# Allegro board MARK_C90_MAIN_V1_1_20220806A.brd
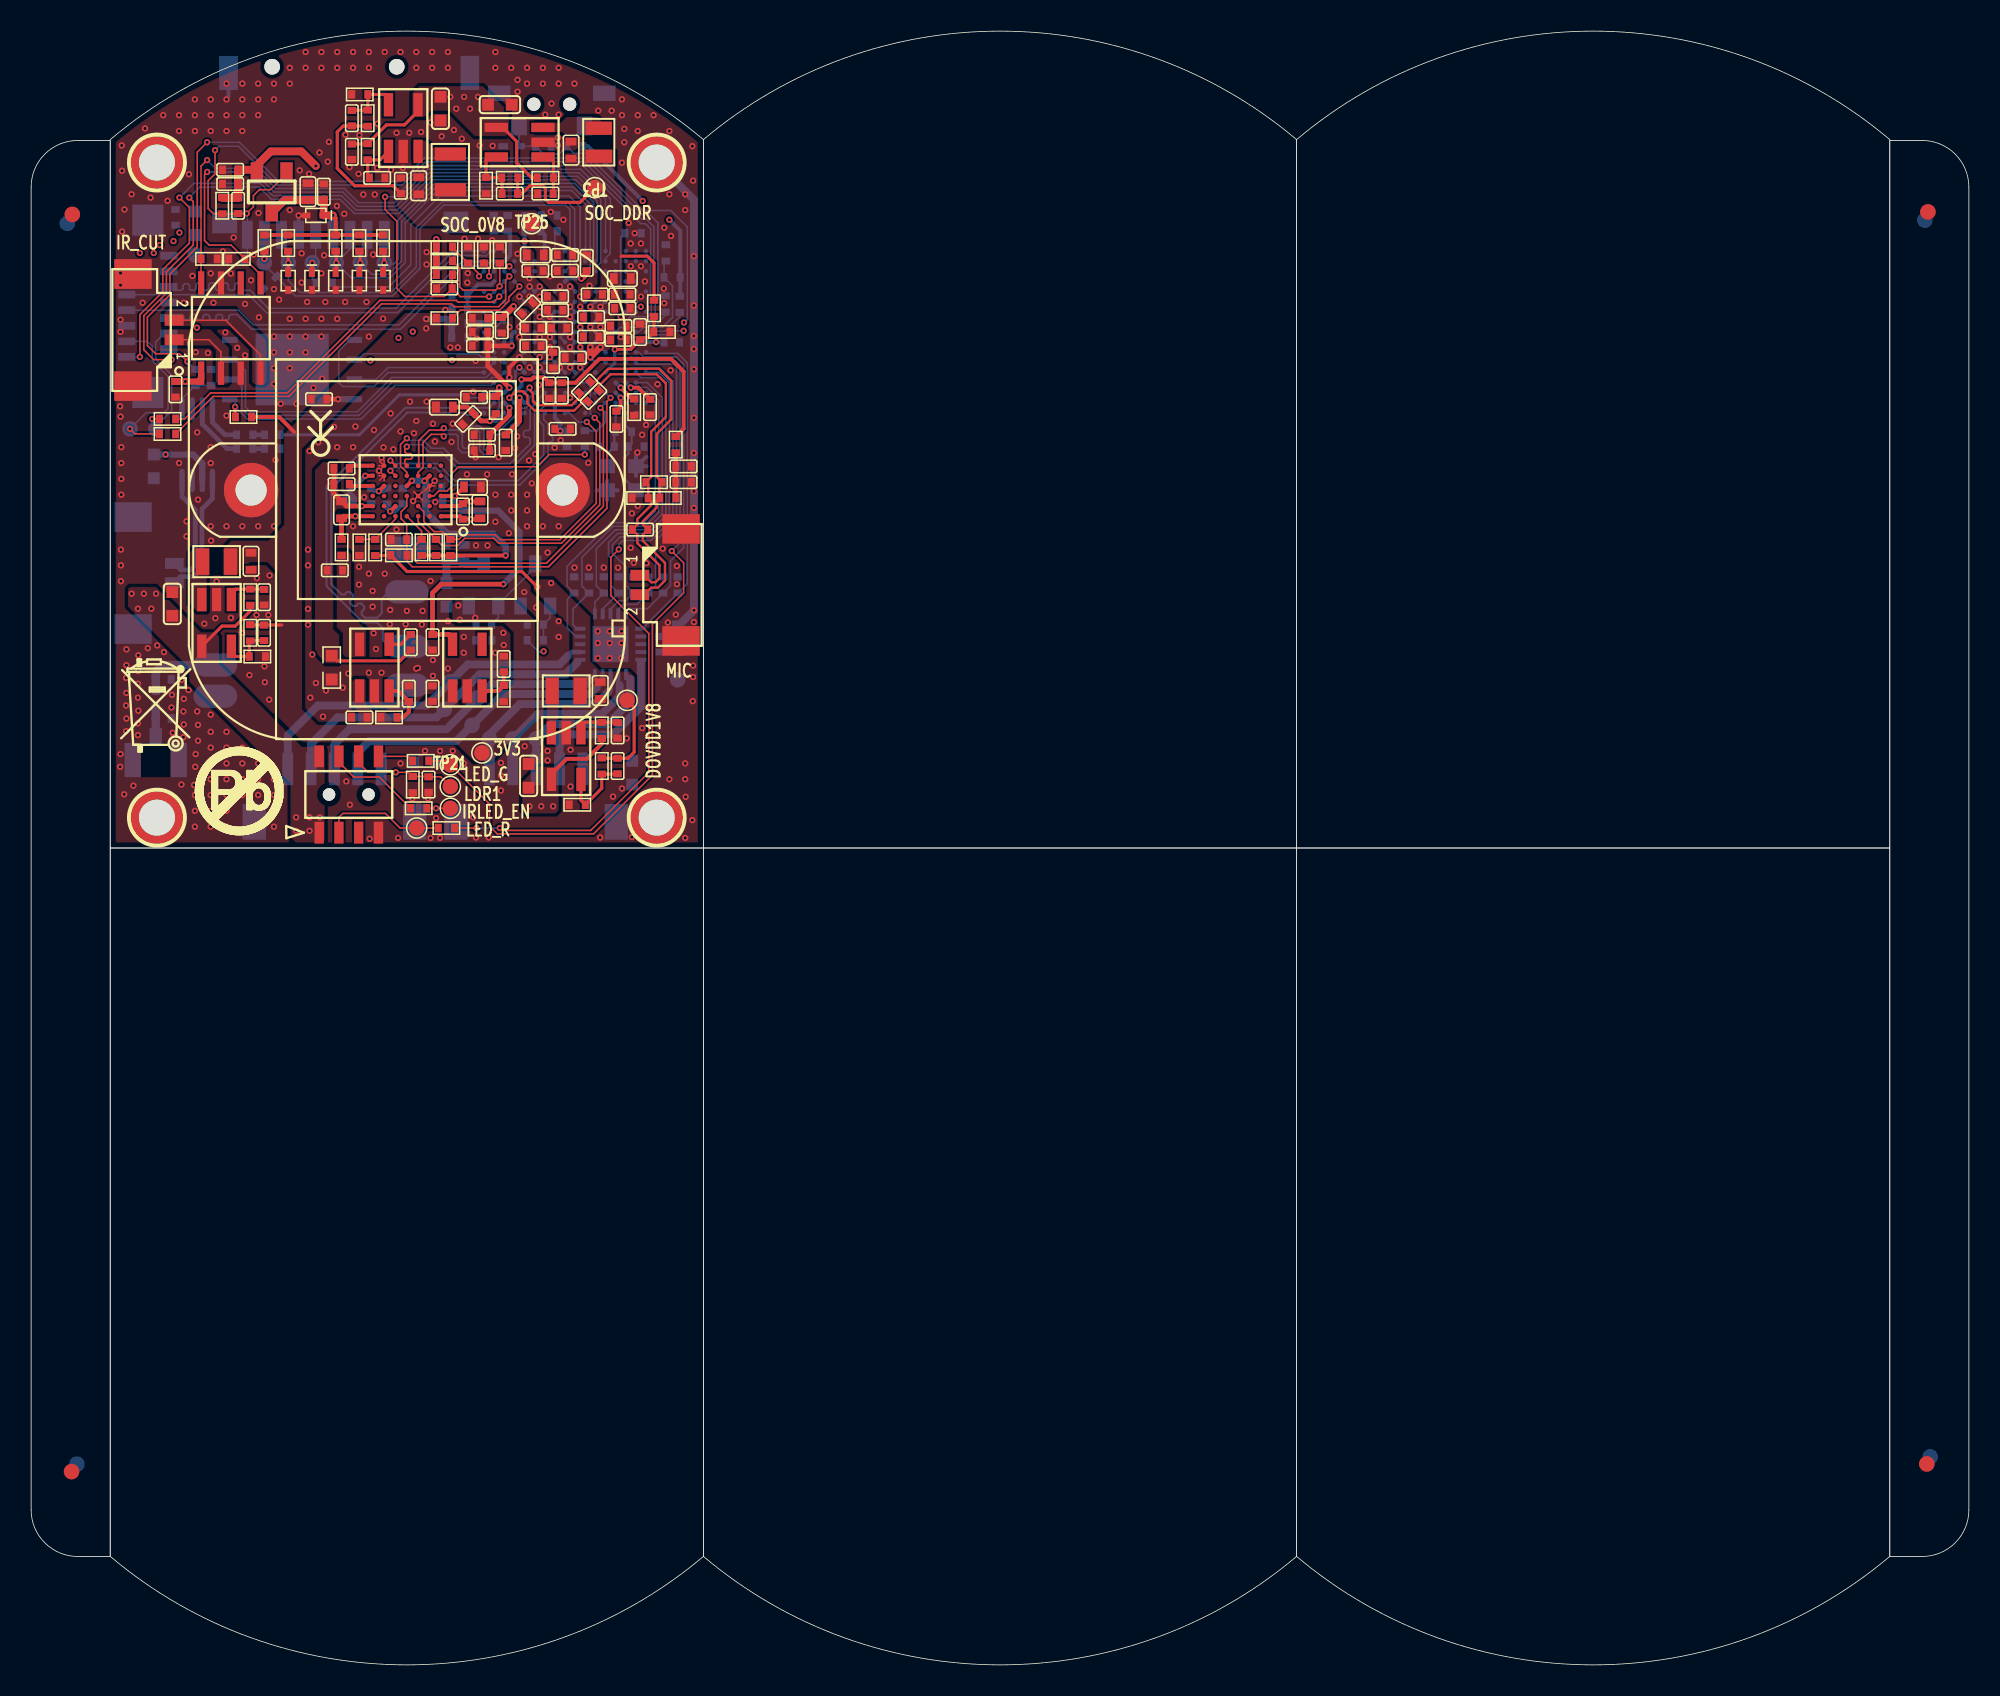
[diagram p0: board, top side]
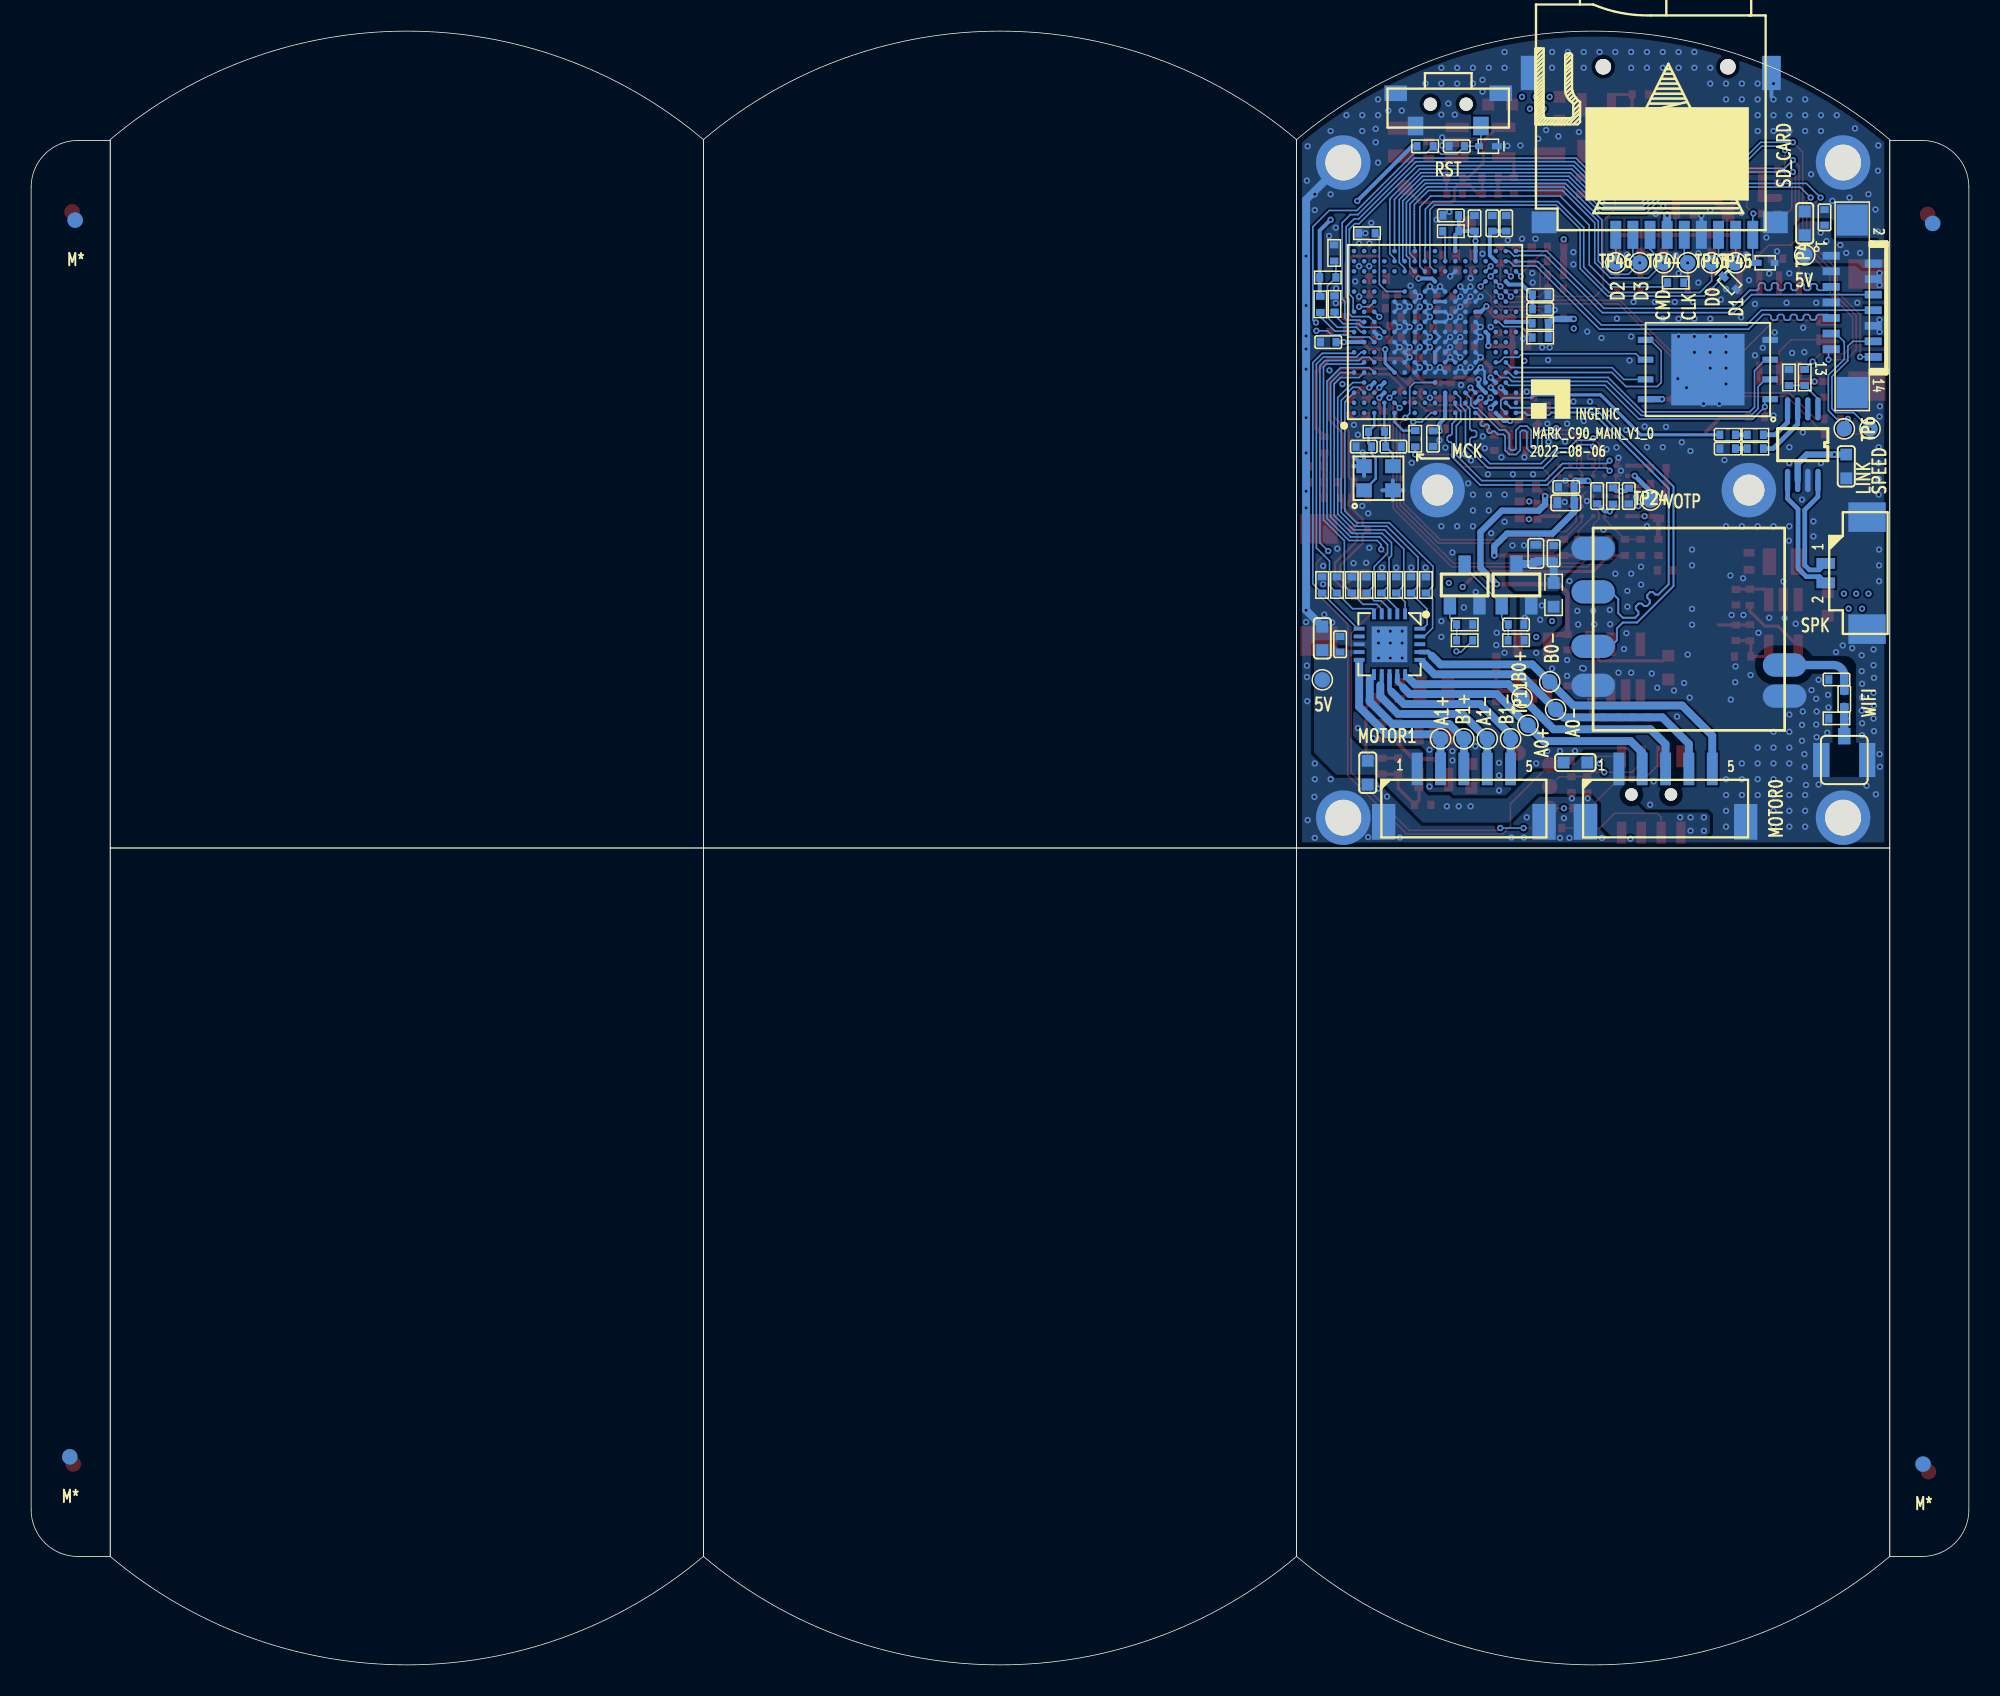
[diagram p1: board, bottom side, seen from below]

Outline 124.46 x 104.99 mm; copper layers: TOP, L2_PWR, L3_GND, BOTTOM. Coordinates in mm from the lower left corner of the outline.
Outline path: 5.08,52.5 5.08,98.02 arc(24.13,104.99) 43.18,98.02 ; 5.08,52.5 5.08,6.97 arc(24.13,0) 43.18,6.97 ; 5.08,52.5 43.18,52.5 ; 5.08,52.5 43.18,52.5 ; 43.18,98.02 43.18,52.5 ; 43.18,98.02 arc(62.23,104.99) 81.28,98.02 ; 43.18,98.02 43.18,52.5 ; 43.18,52.5 43.18,6.97 ; 43.18,52.5 81.28,52.5 ; 43.18,52.5 43.18,6.97 ; 43.18,52.5 81.28,52.5 ; 81.28,98.02 81.28,52.5 ; 81.28,98.02 arc(100.33,104.99) 119.38,98.02 119.38,52.5 ; 81.28,98.02 81.28,52.5 ; 43.18,6.97 arc(62.23,0) 81.28,6.97 ; 81.28,52.5 81.28,6.97 ; 81.28,52.5 119.38,52.5 ; 81.28,52.5 81.28,6.97 ; 81.28,52.5 119.38,52.5 ; 81.28,6.97 arc(100.33,0) 119.38,6.97 119.38,52.5 ; 0,94.97 0,9.96 arc(0.88,7.84) 3,6.97 5.08,6.97 5.08,97.96 3,97.96 arc(0.88,97.09) 0,94.97 ; 119.38,97.96 119.38,6.97 121.46,6.97 arc(123.58,7.84) 124.46,9.96 124.46,94.97 arc(123.58,97.09) 121.46,97.96 119.38,97.96

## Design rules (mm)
net group ENTH_R: nets RD_N RD_P
net group ENTH_T: nets TD_N TD_P
net group MICNL: nets MICNL MINNL
net group MICPL: nets MICPL MINPL
net group USB_D: nets USB_DM USB_DP
net group MIPI_CSI: nets CSI_CLKN CSI_CLKP CSI_DATAN0 CSI_DATAN1 CSI_DATAP0 CSI_DATAP1
net group POWER: nets VDDMSC0

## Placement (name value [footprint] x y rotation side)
C1  10uF/10V-0603  [C0603]  9.07 68.18 90 top
C2  10uF/6.3V  [C0402_E]  24.89 95.05 90 top
C3  100nF/10V  [C0402]  14.96 68.61 270 top
C4  100nF/6.3V  [C0402]  23.75 95.05 90 top
C5  22pF/50V  [C0402]  14.96 66.33 270 top
C6  22pF/50V  [C0402]  20.6 99.4 270 top
C7  10uF/6.3V  [C0402_E]  14.12 70.92 270 top
C8  10uF/10V-0603  [C0603]  26.29 100.01 270 top
C9  100nF/10V  [C0402]  20.6 97.24 270 top
C10  100nF/10V  [C0402]  22.22 95.56 0 top
C11  22pF/50V  [C0402]  37.67 57.77 270 top
C12  10uF/6.3V  [C0402_E]  36.55 62.62 270 top
C13  10uF/10V-0603  [C0603]  31.95 57.13 90 top
C14  100nF/10V  [C0402]  37.67 60.05 270 top
C15  22pF/50V  [C0402]  30.74 94.55 180 top
C16  10uF/6.3V  [C0402_E]  34.68 97.34 90 top
C17  100nF/6.3V  [C0402]  18.49 81.34 0 top
C18  10uF/10V-0603  [C0603]  30.11 100.27 0 top
C20  100nF/10V  [C0402]  33.03 94.55 180 top
C21  12pF/50V  [C0402]  38.86 78.29 180 bottom
C22  100pF/50V  [C0402]  39.12 72.96 0 top
C23  100nF/6.3V  [C0402]  41.91 77.02 0 top
C24  4.7uF/6.3V  [C0402]  41.91 76 0 top
C25  12pF/50V  [C0402]  36.96 78.29 0 bottom
C26  3.3nF/50V  [C0402]  15.49 78.16 0 bottom
C27  3.3nF/50V  [C0402]  15.49 79.05 0 bottom
C28  10uF/10V-0603  [C0603]  7.87 77.02 270 bottom
C29  10uF/10V-0603  [C0603]  25.27 57.99 0 bottom
C30  10uF/10V-0603  [C0603]  10.54 92.64 90 bottom
C31  1uF/6.3V  [C0402]  9.27 81.97 270 top
C32  2.2uF/10V  [C0402]  19.94 75.88 0 top
C33  2.2uF/10V  [C0402]  19.94 76.89 0 top
C34  100nF/6.3V  [C0402]  31.75 92.64 90 bottom
C35  100nF/6.3V  [C0402]  23.62 72.32 0 top
C36  100nF/10V  [C0402]  9.27 93.02 270 bottom
C37  1uF/6.3V  [C0402]  19.51 70.34 180 top
C38  100nF/6.3V  [C0402]  24.26 62.41 90 top
C39  100nF/6.3V  [C0402]  23.88 75.11 90 bottom
C40  10uF/6.3V  [C0402_E]  19.94 74.23 90 top
C41  10uF/6.3V  [C0402_E]  28.83 74.23 90 top
C42  100nF/6.3V  [C0402]  27.74 74.12 90 top
C43  10uF/6.3V  [C0402_E]  25.89 74.68 0 bottom
C44  100nF/6.3V  [C0402]  25.86 75.7 0 bottom
C45  10uF/6.3V  [C0402_E]  28.35 75.7 0 top
C46  100nF/6.3V  [C0402]  21.84 75.11 270 bottom
C47  1uF/6.3V  [C0402]  25.78 65.72 270 top
C48  100nF/6.3V  [C0402]  33.66 87.05 180 top
C49  1uF/6.3V  [C0402]  25.78 62.41 90 top
C50  100nF/6.3V  [C0402]  30.35 64.32 90 top
C51  10uF/10V-0603  [C0603]  41.53 65.97 90 bottom
C52  10nF/6.3V  [C0402]  24.38 65.72 270 top
C53  100nF/6.3V  [C0402]  28.07 80.07 225 top
C54  10uF/6.3V  [C0402_E]  26.54 80.83 180 top
C58  100nF/10V  [C0402]  40.39 65.59 90 bottom
C61  100nF/6.3V  [C0402]  32.26 84.77 0 top
C63  100nF/6.3V  [C0402]  28.45 81.46 180 top
C65  100nF/6.3V  [C0402]  28.83 84.77 180 top
C66  4.7uF/6.3V  [C0402]  28.96 79.05 180 top
C67  100nF/6.3V  [C0402]  28.96 78.04 180 top
C68  4.7uF/6.3V  [C0402]  33.27 81.9 270 top
C69  100nF/6.3V  [C0402]  34.09 81.9 270 top
C70  100nF/6.3V  [C0402]  35.56 82.1 45 top
C71  100nF/6.3V  [C0402]  36.12 81.54 45 top
C72  100nF/6.3V  [C0402]  32.89 97.59 0 bottom
C73  100nF/10V  [C0402]  25.53 56.57 270 top
C74  100nF/6.3V  [C0402]  29.72 92.64 90 bottom
C75  1uF/6.3V  [C0402]  21.08 60.89 180 top
C76  1uF/6.3V  [C0402]  30.61 92.64 90 bottom
C77  10uF/10V-0603  [C0603]  38.61 57.33 270 bottom
C79  100nF/6.3V  [C0402]  27.53 87.13 180 bottom
C83  10pF/50V  [C0402]  8 62.08 270 bottom
C84  10uF/6.3V  [C0402_E]  27.81 71.43 90 bottom
C86  100nF/6.3V  [C0402]  30.48 78.54 270 top
C88  100nF/6.3V  [C0402]  34.42 78.8 270 bottom
C89  100nF/6.3V  [C0402]  26.67 71.43 90 bottom
C90  100nF/6.3V  [C0402]  34.29 89.59 180 top
C91  1uF/6.3V  [C0402]  29.08 66.86 180 bottom
C96  100nF/6.3V  [C0402]  39.75 80.83 270 top
C97  5.6pF/50V  [C0402]  8.5 63.33 180 bottom
C140  100nF/6.3V  [C0402]  28.83 86.54 180 top
C143  1uF/6.3V  [C0402]  30.23 86.09 270 top
C144  100nF/6.3V  [C0402]  35.69 90.1 90 top
C146  10uF/6.3V  [C0402_E]  17.78 94.67 90 top
C147  100nF/6.3V  [C0402]  18.8 94.67 90 top
C148  4.7uF/6.3V  [C0402]  12.78 96.08 180 top
C149  100nF/6.3V  [C0402]  12.78 95.17 180 top
C150  1uF/6.3V  [C0402]  13.29 93.77 270 top
C175  1uF/6.3V  [C0402]  27.53 88.04 180 bottom
C176  100nF/6.3V  [C0402]  26.54 88.45 180 top
C187  100nF/6.3V  [C0402]  34.14 79.43 0 top
C189  100nF/6.3V  [C0402]  28.83 85.66 180 top
C203  10uF/6.3V  [C0402_E]  32.38 90.61 180 top
C206  100nF/6.3V  [C0402]  33.91 85.91 180 top
C212  100nF/6.3V  [C0402]  31.88 87.18 45 top
C213  100nF/6.3V  [C0402]  34.29 90.61 0 top
C214  100nF/6.3V  [C0402]  32.38 89.59 180 top
C215  100nF/6.3V  [C0402]  33.66 87.94 180 top
C216  100nF/6.3V  [C0402]  32.26 85.91 0 top
C217  10nF/6.3V  [C0402]  33.53 83.85 90 top
C218  10nF/6.3V  [C0402]  34.8 84 0 top
C231  100nF/6.3V  [C0402]  37.72 86.04 0 top
C232  100nF/6.3V  [C0402]  37.97 87.18 0 top
C233  10uF/6.3V  [C0402_E]  37.97 89.08 0 top
C234  100nF/6.3V  [C0402]  35.97 86.62 180 top
C238  100nF/6.3V  [C0402]  37.72 85.15 0 top
C239  100nF/6.3V  [C0402]  35.97 85.35 180 top
C240  10nF/6.3V  [C0402]  36.2 88.07 180 top
C241  10nF/6.3V  [C0402]  37.97 88.07 0 top
C244  100nF/6.3V  [C0402]  39.12 85.66 270 top
C248  100nF/6.3V  [C0402]  37.59 80.07 270 top
C250  100nF/6.3V  [C0402]  41.15 85.01 0 bottom
C255  100nF/6.3V  [C0402]  33.27 93.15 0 bottom
D1  ESD5451X  [ESD0402]  30.86 97.59 0 bottom
D2  ESD5451X  [ESD0402]  18.29 93.15 180 top
D3  ESD5451X  [ESD0402]  18.03 88.96 270 top
D4  ESD5451X  [ESD0402]  19.56 88.96 270 top
D5  ESD5451X  [ESD0402]  16.51 88.96 270 top
D6  ESD5451X  [ESD0402]  15.37 88.83 225 bottom
D7  ESD5451X  [ESD0402]  22.61 88.96 270 top
D8  ESD5451X  [ESD0402]  21.08 88.96 270 top
D9  ESD5451X  [ESD0402]  13.08 90.1 180 bottom
FB7  1000ohm/250mA  [FB0402]  29.84 80.96 270 top
HOLE1  T POINT R  [H3D5MM_2D2MM]  8.08 54.45 0 top
HOLE2  T POINT R  [H3D5MM_2D2MM]  40.18 96.55 0 top
HOLE3  T POINT R  [H3D5MM_2D2MM]  8.08 96.55 0 top
HOLE4  T POINT R  [H3D5MM_2D2MM]  40.18 54.45 0 top
J1  CON2 1.25mm LT  [CON2-1D25-LT]  41.19 69.4 90 top
J2  CON2 1.25mm LT  [CON2-1D25-LT]  7.09 70.16 90 bottom
J3  CON14 0.5mm LT  [FPC-CON14-0D5-LT]  7.49 87.31 270 bottom
J4  CON2 1.25mm LT  [CON2-1D25-LT]  7.09 85.78 270 top
J5  Sensor  [IRCUT-32X28-16_8X14_9]  24.13 75.5 270 top
J6  CON5 1.5mm LT  [CON5-1D5-LT]  19.48 55.03 180 bottom
J7  CON5 1.5mm LT  [CON5-1D5-LT]  32.44 55.03 180 bottom
J8  CON8 1.27mm Female  [HEADER4X2FM_1D27_SMD]  20.4 55.93 0 top
J9  IPEX  [ANT3_U_FL_R_SMD]  8 58.15 0 bottom
J32  MICROSD_TF  [TFCARD]  20.43 92.1 0 bottom
L1  2.2uH/2.2A-2520  [L2520]  26.92 95.94 270 top
L2  2.2uH/1.3A-2016  [L2016]  11.91 70.9 180 top
L3  2.2uH/1.3A-2016  [L2016]  34.37 62.59 180 top
L4  2.2uH/1.3A-2016  [L2016]  36.46 97.85 90 top
L5  -  [L0402]  8.5 60.83 0 bottom
M*  -  [unnamed#2]  2.94 12.9 180 bottom
M*#2  -  [unnamed#2]  121.98 13.37 180 bottom
M*#3  -  [unnamed#2]  121.63 92.84 180 bottom
NOREF  -  []  43.21 101.99 0 top
NOREF#2  -  [unnamed#2]  2.6 12.42 0 top
NOREF#3  -  []  102.02 0.05 90 top
NOREF#4  -  []  -8.59 51.34 0 top
NOREF#5  -  [unnamed#2]  2.65 93.21 0 top
NOREF#6  -  []  169.66 233.61 0 top
NOREF#7  -  []  10.54 61.77 0 top
NOREF#8  -  [unnamed#2]  121.83 93.37 0 top
NOREF#9  -  [unnamed#2]  121.76 12.91 0 top
NOREF#10  -  []  5.41 101.89 0 top
NOREF#11  -  []  70.28 210.17 0 top
NOREF#12  -  []  -81.64 -109 0 top
NOREF#13  -  []  119.25 99.96 0 top
NOREF#14  -  []  81 103.03 0 top
NOREF#15  -  []  0 9.96 0 top
NOREF#16  -  [unnamed#2]  2.32 92.63 180 bottom
NOREF#17  -  []  26.86 81.35 180 bottom
Q1  WPM3401  [SOT23]  15.45 94.66 180 top
Q2  WPM3401  [SOT23]  29.06 69.4 180 bottom
Q3  SST3904  [SOT23]  32.38 69.4 180 bottom
R1  100K  [R0402]  14.07 68.61 90 top
R2  100K  [R0402]  21.62 97.24 270 top
R3  150K/1%  [R0402]  14.07 66.33 90 top
R4  33.2K/1%  [R0402]  14.53 64.8 180 top
R5  100K/1%  [R0402]  21.62 99.4 270 top
R6  300K/1%  [R0402]  21.11 100.92 180 top
R7  100K  [R0402]  36.65 60.05 90 top
R8  200K/1%  [R0402]  36.65 57.77 90 top
R9  100K/1%  [R0402]  35.08 55.28 0 top
R10  100K  [R0402]  33.03 95.57 0 top
R11  150K/1%  [R0402]  30.74 95.57 0 top
R12  10K  [R0402]  13.64 80.19 0 top
R13  120K/1%  [R0402]  29.22 95.06 90 top
R14  33R  [R0402]  38.73 80.83 270 top
R15  2.2K  [R0402]  39.12 74.99 180 top
R16  10K  [R0402]  27.53 86.21 180 bottom
R17  1M  [R0402]  38.05 79.25 0 bottom
R18  10K  [R0402]  40 76 0 top
R19  2.2K  [R0402]  40.89 74.99 180 top
R20  0R  [R0402]  41.4 78.42 90 top
R21  10K  [R0402]  11.56 82.73 90 bottom
R22  0R  [R0402]  10.54 82.73 270 bottom
R23  10K  [R0402]  27.53 85.3 180 bottom
R24  68K/1%  [R0402]  13.72 78.16 0 bottom
R26  68K/1%  [R0402]  13.72 79.05 0 bottom
R27  0R  [R0402]  22.86 75.11 270 bottom
R28  10K  [R0402]  11.43 90.35 0 top
R29  10K  [R0402]  13.21 90.35 180 top
R30  4.7K  [R0402]  26 71.81 90 top
R32  4.7K  [R0402]  26.93 71.81 90 top
R33  10K  [R0402]  25.08 71.81 90 top
R34  10K  [R0402]  23.62 71.3 0 top
R35  10K  [R0402]  22.1 71.81 90 top
R36  4.7K  [R0402]  21.08 71.81 90 top
R37  0R  [R0402]  19.94 71.81 90 top
R38  150K  [R0402]  22.99 60.89 0 top
R39  0R-0603  [R0603]  19.3 64.09 270 top
R40  100K  [R0402]  30.35 62.41 90 top
R42  100K  [R0402]  34.87 69.4 90 bottom
R43  100K  [R0402]  35.83 69.4 90 bottom
R44  100K  [R0402]  36.78 69.4 270 bottom
R45  100K  [R0402]  37.73 69.4 270 bottom
R46  100K  [R0402]  38.68 69.4 270 bottom
R47  100K  [R0402]  39.64 69.4 270 bottom
R48  100K  [R0402]  40.59 69.4 270 bottom
R49  100K  [R0402]  41.54 69.4 270 bottom
R50  1K  [R0402]  28.07 90.61 90 top
R51  10K  [R0402]  26.54 91.12 180 top
R52  10K  [R0402]  26.54 89.34 180 top
R53  10K  [R0402]  34.92 97.59 180 bottom
R54  0R  [R0402]  26.67 53.78 180 top
R55  1K  [R0402]  24.89 55.05 180 top
R56  0R  [R0402]  25.02 58.1 0 top
R57  33R  [R0402]  35.56 78.8 90 bottom
R58  33.2K/1%  [R0402]  24.51 56.57 90 top
R59  100K  [R0402]  41.66 87.43 90 bottom
R60  100K  [R0402]  41.17 89.16 0 bottom
R61  100K  [R0402]  40.77 90.74 270 bottom
R68  0R-0603  [R0603]  26.67 68.76 90 bottom
R69  100K  [R0402]  29.08 65.84 180 bottom
R70  1K  [R0402]  32.38 65.84 0 bottom
R71  10K  [R0402]  32.38 66.86 0 bottom
R75  240R/1%  [R0402]  40.74 87.46 90 bottom
R99  300R  [R0402]  8.76 80.07 0 top
R100  300R  [R0402]  8.76 79.1 0 top
R207  33R  [R0402]  18.83 88.83 0 bottom
R209  100K  [R0402]  16.51 91.37 270 top
R210  100K  [R0402]  19.56 91.37 270 top
R211  100K  [R0402]  14.99 91.37 270 top
R212  100K  [R0402]  22.61 91.37 270 top
R213  100K  [R0402]  21.08 91.37 270 top
R214  100K  [R0402]  12.28 93.77 270 top
R312  2.49K/1%  [R0402]  29.08 90.61 90 top
R313  10K  [R0402]  26.54 86.54 180 top
R314  10K  [R0402]  26.54 90.23 180 top
R315  1K  [R0402]  30.1 90.61 90 top
R343  1K  [R0402]  33.27 92.13 0 bottom
R345  240R/1%  [R0402]  38.66 92.01 0 bottom
R346  10K/1%  [R0402]  40 87.18 90 top
R347  10K/1%  [R0402]  40.51 85.66 180 top
SW2  ST1112A  [SW2_SMD_ST1112A]  33.44 100.3 180 bottom
TP1  1mm_SMD  [TEST_SMD]  28.96 58.6 270 top
TP2  1mm_SMD  [TEST_SMD]  38.28 61.98 0 top
TP3  1mm_SMD  [TEST_SMD]  36.2 94.93 180 top
TP4  1mm_SMD  [TEST_SMD]  10.54 90.61 90 bottom
TP5  1mm_SMD  [TEST_SMD]  8 79.43 90 bottom
TP6  1mm_SMD  [TEST_SMD]  6.35 79.43 90 bottom
TP9  1mm_SMD  [TEST_SMD]  26.92 63.18 270 bottom
TP10  1mm_SMD  [TEST_SMD]  26.54 61.4 270 bottom
TP11  1mm_SMD  [TEST_SMD]  28.7 62.16 90 bottom
TP12  1mm_SMD  [TEST_SMD]  28.32 60.38 90 bottom
TP13  1mm_SMD  [TEST_SMD]  41.53 63.3 270 bottom
TP14  1mm_SMD  [TEST_SMD]  29.44 59.51 180 bottom
TP15  1mm_SMD  [TEST_SMD]  30.94 59.51 180 bottom
TP16  1mm_SMD  [TEST_SMD]  32.44 59.51 180 bottom
TP17  1mm_SMD  [TEST_SMD]  33.94 59.51 180 bottom
TP18  1mm_SMD  [TEST_SMD]  24.77 53.78 0 top
TP19  1mm_SMD  [TEST_SMD]  26.92 55.05 0 top
TP20  1mm_SMD  [TEST_SMD]  26.92 56.45 0 top
TP21  1mm_SMD  [TEST_SMD]  26.92 57.84 0 top
TP24  1mm_SMD  [TEST_SMD]  20.45 74.86 180 bottom
TP25  1mm_SMD  [TEST_SMD]  32.16 92.61 0 top
TP43  1mm_SMD  [TEST_SMD]  16.52 90.1 180 bottom
TP44  1mm_SMD  [TEST_SMD]  19.6 90.1 180 bottom
TP45  1mm_SMD  [TEST_SMD]  14.98 90.1 180 bottom
TP46  1mm_SMD  [TEST_SMD]  22.68 90.1 180 bottom
TP47  1mm_SMD  [TEST_SMD]  21.14 90.1 90 bottom
TP48  1mm_SMD  [TEST_SMD]  18.06 90.1 90 bottom
U1  LN5058  [SOT23-5]  11.91 66.96 180 top
U2  ETA3409  [SOT23-5]  23.9 98.76 0 top
U3  LN5058  [SOT23-5]  34.37 58.4 180 top
U4  T41 BGA232  [BGA232_0D65_T41]  34.29 85.66 90 bottom
U5  LN5058  [SOT23-5]  31.38 97.85 90 top
U6  CS8302M  [MSOP8_0D65]  10.67 78.42 0 bottom
U7  GC4663  [BGA41_0D73X0D65_GC4663]  24.05 75.52 180 top
U9  BA6208  [SOP8_1D27]  12.83 85.91 90 top
U10  SGM2019-2.8YN5G  [SOT23-5]  22.05 64.09 0 top
U11  S-1339D13  [SOT23-5]  28.02 64.09 0 top
U12  ULN2803A  [QFN20L_0D5_ULN2803]  37.21 65.59 270 bottom
U13  GD5F1GQ5UEYIGR  [WSON8_1D27_8X6]  16.76 83.24 0 bottom
U14  BL-M8188FU3-B  [LCC6_BLM8188FU3]  17.98 66.55 180 bottom
Y1  24M 2016  [CRY_2D5X2D0]  37.92 76.26 180 bottom

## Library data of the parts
C1-C18 C20-C54 C58 C61 C63 C65-C69 C72-C77 C79 C83 C84 C86 C88-C91 C96 C97 C140 C143 C144 C146-C150 C175 C176 C187 C189 C203 C206 C212-C218 C231-C234 C238-C241 C244 C248 C250 C255 = CAP
C70 C71 = CAP: signal model: CAP_C0402_100NF/6.3V_100nF/6.3V
D1-D9 = ESD
FB7 = BEAD
HOLE1-HOLE4 = T POINT R
J1 J2 J4 = CON_2X1
J3 = FPCCON_7X2
J5 = Sensor
J6 J7 = CON_5X1
J8 = HEADER_4X2
J9 = IPEX
J32 = MMC_SD
L1-L5 = INDUCTOR
Q1 Q2 = P_MOS
Q3 = NPN
R1-R24 R26-R30 R32-R40 R42-R61 R68-R71 R75 R99 R100 R207 R209-R214 R312-R315 R343 R345-R347 = RES
SW2 = SW2_C
TP1-TP6 TP9-TP21 TP24 TP25 TP43-TP48 = TP
U1-U3 U5 = SY8088
U4 = T41_BGA232
U6 = CS8302
U7 = GC4663
U9 = BA6208
U10 U11 = SGM2019
U12 = ULN2803A-QFN203PDB3
U13 = SPI_NAND
U14 = USBWIFI_T
Y1 = XTAL_P4

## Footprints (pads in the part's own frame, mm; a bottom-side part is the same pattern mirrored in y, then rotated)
ANT3_U_FL_R_SMD
  rect 1.05x2.2 smd: 1(-1.475,0) 2(1.475,0)
  rect 0.8x1.05 smd: 3(0,-1.525)
BGA41_0D73X0D65_GC4663
  round 0.3 smd: A1(-2.27,1.707) A2(-1.54,1.707) A3(-0.81,1.707) A4(-0.08,1.707) A5(0.65,1.707) A6(1.38,1.707) A7(2.11,1.707) B1(-2.27,1.057) B2(-1.54,1.057) B3(-0.81,1.057) B5(0.65,1.057) B6(1.38,1.057) B7(2.11,1.057) C1(-2.27,0.407) C2(-1.54,0.407) C3(-0.81,0.407) C4(-0.08,0.407) C5(0.65,0.407) C6(1.38,0.407) C7(2.11,0.407) D1(-2.27,-0.243) D2(-1.54,-0.243) D3(-0.81,-0.243) D4(-0.08,-0.243) D5(0.65,-0.243) D6(1.38,-0.243) D7(2.11,-0.243) E1(-2.27,-0.893) E2(-1.54,-0.893) E3(-0.81,-0.893) E4(-0.08,-0.893) E5(0.65,-0.893) E6(1.38,-0.893) E7(2.11,-0.893) F1(-2.27,-1.543) F2(-1.54,-1.543) F3(-0.81,-1.543) F4(-0.08,-1.543) F5(0.65,-1.543) F6(1.38,-1.543) F7(2.11,-1.543)
BGA232_0D65_T41
  round 0.3 smd: A1(-5.2,5.2) A2(-4.55,5.2) A3(-3.9,5.2) A5(-2.6,5.2) A7(-1.3,5.2) A9(0,5.2) A11(1.3,5.2) A13(2.6,5.2) A15(3.9,5.2) A16(4.55,5.2) A17(5.2,5.2) B1(-5.2,4.55) B2(-4.55,4.55) B3(-3.9,4.55) B4(-3.25,4.55) B5(-2.6,4.55) B6(-1.95,4.55) B7(-1.3,4.55) B8(-0.65,4.55) B9(0,4.55) B10(0.65,4.55) B11(1.3,4.55) B12(1.95,4.55) B13(2.6,4.55) B14(3.25,4.55) B15(3.9,4.55) B16(4.55,4.55) B17(5.2,4.55) C1(-5.2,3.9) C2(-4.55,3.9) C3(-3.9,3.9) C4(-3.25,3.9) C5(-2.6,3.9) C6(-1.95,3.9) C7(-1.3,3.9) C8(-0.65,3.9) C9(0,3.9) C10(0.65,3.9) C11(1.3,3.9) C12(1.95,3.9) C13(2.6,3.9) C14(3.25,3.9) C15(3.9,3.9) C16(4.55,3.9) C17(5.2,3.9) D2(-4.55,3.25) D3(-3.9,3.25) D4(-3.25,3.25) D9(0,3.25) D14(3.25,3.25) D15(3.9,3.25) D16(4.55,3.25) E1(-5.2,2.6) E2(-4.55,2.6) E3(-3.9,2.6) E5(-2.6,2.6) E6(-1.95,2.6) E7(-1.3,2.6) E8(-0.65,2.6) E9(0,2.6) E10(0.65,2.6) E11(1.3,2.6) E12(1.95,2.6) E15(3.9,2.6) E16(4.55,2.6) E17(5.2,2.6) F2(-4.55,1.95) F3(-3.9,1.95) F5(-2.6,1.95) F6(-1.95,1.95) F7(-1.3,1.95) F8(-0.65,1.95) F9(0,1.95) F10(0.65,1.95) F11(1.3,1.95) F12(1.95,1.95) F13(2.6,1.95) F15(3.9,1.95) F16(4.55,1.95) G1(-5.2,1.3) G2(-4.55,1.3) G3(-3.9,1.3) G5(-2.6,1.3) G6(-1.95,1.3) G7(-1.3,1.3) G8(-0.65,1.3) G9(0,1.3) G10(0.65,1.3) G11(1.3,1.3) G12(1.95,1.3) G13(2.6,1.3) G15(3.9,1.3) G16(4.55,1.3) G17(5.2,1.3) H2(-4.55,0.65) H3(-3.9,0.65) H5(-2.6,0.65) H6(-1.95,0.65) H7(-1.3,0.65) H8(-0.65,0.65) H9(0,0.65) H10(0.65,0.65) H11(1.3,0.65) H12(1.95,0.65) H13(2.6,0.65) H15(3.9,0.65) H16(4.55,0.65) J1(-5.2,0) J2(-4.55,0) J3(-3.9,0) J4(-3.25,0) J5(-2.6,0) J6(-1.95,0) J7(-1.3,0) J8(-0.65,0) J9(0,0) J10(0.65,0) J11(1.3,0) J12(1.95,0) J13(2.6,0) J14(3.25,0) J15(3.9,0) J16(4.55,0) J17(5.2,0) K2(-4.55,-0.65) K3(-3.9,-0.65) K5(-2.6,-0.65) K6(-1.95,-0.65) K7(-1.3,-0.65) K8(-0.65,-0.65) K9(0,-0.65) K10(0.65,-0.65) K11(1.3,-0.65) K12(1.95,-0.65) K13(2.6,-0.65) K15(3.9,-0.65) K16(4.55,-0.65) L1(-5.2,-1.3) L2(-4.55,-1.3) L3(-3.9,-1.3) L5(-2.6,-1.3) L6(-1.95,-1.3) L7(-1.3,-1.3) L8(-0.65,-1.3) L9(0,-1.3) L10(0.65,-1.3) L11(1.3,-1.3) L12(1.95,-1.3) L13(2.6,-1.3) L15(3.9,-1.3) L16(4.55,-1.3) L17(5.2,-1.3) M2(-4.55,-1.95) M3(-3.9,-1.95) M5(-2.6,-1.95) M6(-1.95,-1.95) M7(-1.3,-1.95) M8(-0.65,-1.95) M9(0,-1.95) M10(0.65,-1.95) M11(1.3,-1.95) M12(1.95,-1.95) M13(2.6,-1.95) M15(3.9,-1.95) M16(4.55,-1.95) N1(-5.2,-2.6) N2(-4.55,-2.6) N3(-3.9,-2.6) N5(-2.6,-2.6) N6(-1.95,-2.6) N7(-1.3,-2.6) N8(-0.65,-2.6) N9(0,-2.6) N10(0.65,-2.6) N11(1.3,-2.6) N12(1.95,-2.6) N13(2.6,-2.6) N15(3.9,-2.6) N16(4.55,-2.6) N17(5.2,-2.6) P2(-4.55,-3.25) P3(-3.9,-3.25) P4(-3.25,-3.25) P9(0,-3.25) P14(3.25,-3.25) P15(3.9,-3.25) P16(4.55,-3.25) R1(-5.2,-3.9) R2(-4.55,-3.9) R3(-3.9,-3.9) R4(-3.25,-3.9) R5(-2.6,-3.9) R6(-1.95,-3.9) R7(-1.3,-3.9) R8(-0.65,-3.9) R9(0,-3.9) R10(0.65,-3.9) R11(1.3,-3.9) R12(1.95,-3.9) R13(2.6,-3.9) R14(3.25,-3.9) R15(3.9,-3.9) R16(4.55,-3.9) R17(5.2,-3.9) T1(-5.2,-4.55) T2(-4.55,-4.55) T3(-3.9,-4.55) T4(-3.25,-4.55) T5(-2.6,-4.55) T6(-1.95,-4.55) T7(-1.3,-4.55) T8(-0.65,-4.55) T9(0,-4.55) T10(0.65,-4.55) T11(1.3,-4.55) T12(1.95,-4.55) T13(2.6,-4.55) T14(3.25,-4.55) T15(3.9,-4.55) T16(4.55,-4.55) T17(5.2,-4.55) U1(-5.2,-5.2) U2(-4.55,-5.2) U3(-3.9,-5.2) U5(-2.6,-5.2) U7(-1.3,-5.2) U9(0,-5.2) U11(1.3,-5.2) U13(2.6,-5.2) U15(3.9,-5.2) U16(4.55,-5.2) U17(5.2,-5.2)
C0402
  rect 0.45x0.55 smd: 1(-0.5,0) 2(0.5,0)
C0402_E
  rect 0.5x0.7 smd: 1(-0.545,0) 2(0.545,0)
C0603
  rect 0.76x0.76 smd: 1(-0.762,0) 2(0.762,0)
CON2-1D25-LT
  rect 0.7x1.2 smd: 1(0.625,2.1) 2(-0.625,2.1)
  rect 1.9x2.4 smd: 3(-3.6,-0.55) 4(3.6,-0.55)
CON5-1D5-LT
  rect 0.7x2.1 smd: 1(-3,2.55) 2(-1.5,2.55) 3(0,2.55) 4(1.5,2.55) 5(3,2.55)
  rect 1.5x2.3 smd: 6(-5.15,-0.85) 7(5.15,-0.85)
CRY_2D5X2D0
  rect 1x0.9 smd: 1(-0.925,-0.775) 2(0.925,-0.775) 3(0.925,0.775) 4(-0.925,0.775)
ESD0402
  rect 0.62x0.4 smd: 1(-0.54,0)
  rect 0.5x0.4 smd: 2(0.6,0)
FB0402
  rect 0.45x0.55 smd: 1(-0.55,0) 2(0.55,0)
FPC-CON14-0D5-LT
  rect 0.5x1.1 smd: 1(-3.25,-1.35) 2(-2.75,1.35) 3(-2.25,-1.35) 4(-1.75,1.35) 5(-1.25,-1.35) 6(-0.75,1.35) 7(-0.25,-1.35) 8(0.25,1.35) 9(0.75,-1.35) 10(1.25,1.35) 11(1.75,-1.35) 12(2.25,1.35) 13(2.75,-1.35) 14(3.25,1.35)
  rect 2x2 smd: 15(-5.54,0) 16(5.54,0)
H3D5MM_2D2MM
  round 3.5 hole 2.311: 1(0,0)
HEADER4X2FM_1D27_SMD
  round 0.8 hole 0.8 unplated: (-1.27,0) (1.27,0)
  rect 0.6x1.4 smd: 1(-1.905,-2.45) 2(-1.905,2.45) 3(-0.635,-2.45) 4(-0.635,2.45) 5(0.635,-2.45) 6(0.635,2.45) 7(1.905,-2.45) 8(1.905,2.45)
IRCUT-32X28-16_8X14_9
  round 3.5 hole 2: 1(0,10) 2(0,-10)
L0402
  rect 0.45x0.55 smd: 1(-0.5,0) 2(0.5,0)
L2016
  rect 0.85x1.7 smd: 1(0.9,0) 2(-0.9,0)
L2520
  rect 0.85x2 smd: 1(-1.15,0) 2(1.15,0)
LCC6_BLM8188FU3
  oval 2.8x1.5 smd: 1(-6.15,-3.6) 2(-6.15,-1.1) 3(-6.15,2.4) 4(-6.15,5.2) 5(6.15,-2.3) 6(6.15,-4.3)
MSOP8_0D65
  oval 0.35x1.5 smd: 1(-0.975,-2.3) 2(-0.325,-2.3) 3(0.325,-2.3) 4(0.975,-2.3) 5(0.975,2.3) 6(0.325,2.3) 7(-0.325,2.3) 8(-0.975,2.3)
QFN20L_0D5_ULN2803
  rect 0.7x0.25 smd: 1(-1.95,1) 2(-1.95,0.5) 3(-1.95,0) 4(-1.95,-0.5) 5(-1.95,-1) 11(1.95,-1) 12(1.95,-0.5) 13(1.95,0) 14(1.95,0.5) 15(1.95,1)
  rect 0.25x0.7 smd: 6(-1,-1.95) 7(-0.5,-1.95) 8(0,-1.95) 9(0.5,-1.95) 10(1,-1.95) 16(1,1.95) 17(0.5,1.95) 18(0,1.95) 19(-0.5,1.95) 20(-1,1.95)
  rect 2.3x2.3 smd: 21(0,0)
R0402
  rect 0.45x0.55 smd: 1(-0.52,0) 2(0.52,0)
R0603
  rect 0.76x0.76 smd: 1(-0.762,0) 2(0.762,0)
SOP8_1D27
  rect 1.5x0.4 smd: 1(-2.9,1.905) 2(-2.9,0.635) 3(-2.9,-0.635) 4(-2.9,-1.905) 5(2.9,-1.905) 6(2.9,-0.635) 7(2.9,0.635) 8(2.9,1.905)
SOT23
  rect 0.8x1.1 smd: 1(-0.95,-1.35) 2(0.95,-1.35) 3(0,1.35)
SOT23-5
  rect 0.6x1.5 smd: 1(-0.95,-1.5) 2(0,-1.5) 3(0.95,-1.5) 4(0.95,1.5) 5(-0.95,1.5)
SW2_SMD_ST1112A
  round 0.85 hole 0.85 unplated: (-1.15,0) (1.15,0)
  rect 1x1.2 smd: 1(-2.1,-1.4) 2(2.1,-1.4)
  rect 1.45x1 smd: 3(-3.375,0.7) 4(3.375,0.7)
TEST_SMD
  round 1 smd: 1(0,0)
TFCARD
  round 1 hole 1 unplated: (-4.95,-10.6) (3.05,-10.6)
  rect 0.7x1.8 smd: 1(2.25,0.2) 2(1.15,0.2) 3(0.05,0.2) 4(-1.05,0.2) 5(-2.15,0.2) 6(-3.25,0.2) 7(-4.35,0.2) 8(-5.45,0.2) 9(-6.55,0.2)
  rect 1.6x1.4 smd: 10(-8,-0.6) 13(6.85,-0.6)
  rect 1.2x2.2 smd: 11(-7.75,-10.2) 12(7.75,-10.2)
unnamed#2
  round 1 smd: 1(0,0)
WSON8_1D27_8X6
  rect 1x0.4 smd: 1(-4,1.905) 2(-4,0.635) 3(-4,-0.635) 4(-4,-1.905) 5(4,-1.905) 6(4,-0.635) 7(4,0.635) 8(4,1.905)
  rect 4.7x4.6 smd: 9(0,0)

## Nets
2V8: C37.1 R37.1 U10.5(VOUT)
AGND: C32.1 C33.1 C37.2 C40.2 C41.2 C42.2 C52.2 R39.1 U7.B1(AGND_1) U7.B7(AGND_2)
AVDD2V8: C40.1 C41.1 C42.1 R37.2 U7.A1(AVDD_1) U7.A7(AVDD_2)
DVDD1V2OUT: C79.1 C175.1 U4.T14(DVDD1V2OUT)
DVDD1V3: C45.1 C46.1 C47.1 R27.1 U7.C1(DVDD_1) U7.D6(DVDD_2) U11.5(VOUT)
GND: C1.2 C2.2 C3.2 C4.2 C7.2 C8.2 C9.2 C10.2 C12.2 C13.2 C14.2 C16.2 C17.1 C18.2 C20.2 C21.1 C23.2 C24.2 C25.1 C26.2 C28.2 C29.2 C30.2 C31.2 C34.2 C35.1 C36.1 C38.2 C39.2 C43.2 C44.2 C45.2 C46.2 C47.2 C48.2 C49.2 C50.2 C51.2 C53.2 C54.2 C58.2 C61.2 C63.2 C65.2 C66.2 C67.2 C68.2 C69.2 C72.2 C73.2 C74.2 C75.2 C76.2 C77.2 C79.2 C84.2 C86.2 C88.2 C89.2 C90.1 C96.2 C97.1 C140.2 C143.2 C144.2 C146.2 C147.2 C148.2 C149.2 C175.2 C176.2 C187.2 C189.2 C203.2 C206.2 C212.2 C213.2 C214.2 C215.2 C216.2 C217.2 C218.2 C231.2 C232.2 C233.2 C234.2 C238.2 C239.2 C240.2 C241.2 C244.1 C248.2 C250.2 C255.2 D1.1(ANODE) D2.2(CATHODE) D3.2(CATHODE) D4.2(CATHODE) D5.2(CATHODE) D6.2(CATHODE) D7.2(CATHODE) D8.2(CATHODE) D9.2(CATHODE) HOLE1.1(TP) HOLE2.1(TP) HOLE3.1(TP) HOLE4.1(TP) J1.3(S1) J1.4(S2) J2.3(S1) J2.4(S2) J3.3 J3.4 J3.7 J3.10 J3.15(S1) J3.16(S2) J4.3(S1) J4.4(S2) J5.1(HOL1) J5.2(HOL2) J6.6(S1) J6.7(S2) J7.6(S1) J7.7(S2) J8.7 J9.1 J9.2 J32.6(VSS2) J32.10(GND_2) J32.11(GND_1) J32.12(PAD1) J32.13(PAD2) L5.2 Q3.2(EMITTER) R4.1 R6.2 R9.1 R13.1 R14.2 R15.2 R21.2 R28.2 R29.2 R36.1 R39.2 R42.2 R43.2 R44.1 R45.1 R46.1 R47.1 R48.1 R49.1 R50.2 R58.1 R61.1 R71.1 R75.2 R312.2 R315.2 R345.2 R347.1 SW2.1 SW2.3 SW2.4 U1.2(GND) U2.2(GND) U3.2(GND) U4.C9(DDRPLL_VSSA) U4.G5(PLL_AVSS) U4.G6(VSS1) U4.G7(VSS2) U4.G8(VSS3) U4.G9(VSS4) U4.G10(VSS5) U4.G11(VSS6) U4.G12(VSS7) U4.G13(VSS8) U4.J6(VSS9) U4.J7(VSS10) U4.J8(VSS11) U4.J9(VSS12) U4.J10(VSS13) U4.J11(VSS14) U4.J12(VSS15) U4.K6(VSS16) U4.K7(VSS17) U4.K8(VSS18) U4.K9(VSS19) U4.K10(VSS20) U4.K11(VSS21) U4.K12(VSS22) U4.L6(VSS23) U4.L7(VSS24) U4.L8(VSS25) U4.L9(VSS26) U4.L10(VSS27) U4.L11(VSS28) U4.L12(VSS29) U4.M7(VSS30) U4.M8(VSS31) U4.M9(VSS32) U4.M10(VSS33) U4.M11(VSS34) U4.M12(VSS35) U4.M13(VSS36) U4.N5(CSI_VSSA) U4.N12(VSS37) U4.N13(SADC_AGND) U4.P4(CODEC_AVSS) U5.2(GND) U6.7(GND) U7.C3(DOGND_1) U7.D2(DOGND_2) U7.E6(DOGND_3) U7.F6(DOGND_4) U9.3(GND0) U9.7(GND1) U10.2(GND) U11.2(GND) U12.8(GND) U12.21(E PAD) U13.4(GND) U13.9(E-PAD) U14.1(GND1) U14.6(GND2) Y1.2 Y1.4
VCC_5V: C1.1 C8.1 C9.1 C13.1 C18.1 C28.1 C29.1 C30.1 C31.1 C36.2 C51.1 C58.1 C77.1 J3.1 J3.2 J6.1 J7.1 J8.1 J8.2 R1.1 R2.1 R7.1 R10.1 TP4.1 TP13.1 U1.4(IN) U2.4(IN) U3.4(IN) U5.4(IN) U6.6(VDD) U9.1(VCC) U12.9(COM)
VDDMSC0: C146.1 C147.1 D2.1(ANODE) J32.4(VDD) Q1.3(DRAIN) R209.1 R210.1 R211.1 R212.1 R213.1
A0+: J6.2 TP12.1 U12.14(4C)
A0-: J6.4 TP10.1 U12.16(2C)
A1+: J7.2 TP17.1 U12.10(8C)
A1-: J7.4 TP15.1 U12.12(6C)
B0+: J6.3 TP11.1 U12.15(3C)
B0-: J6.5 TP9.1 U12.17(1C)
B1+: J7.3 TP16.1 U12.11(7C)
B1-: J7.5 TP14.1 U12.13(5C)
BOOTSEL0: R59.1 U4.A9(BOOT_SEL0_PC00)
BOOTSEL1: R60.1 R61.2 U4.B9(BOOT_SEL1_PC01)
CODEC_AVDD: C53.1 C54.1 FB7.2 U4.R1(CODEC_AVDD)
CSI_CLKN: U4.M2(CSI_CLKN_DVP_D4) U7.E4(MCN)
CSI_CLKP: U4.L3(CSI_CLKP_DVP_D5) U7.F4(MCP)
CSI_DATAN0: U4.L2(CSI_DATAN0_DVP_D0) U7.F5(MDN0)
CSI_DATAN1: U4.N1(CSI_DATAN1_DVP_D2) U7.E3(MDN1)
CSI_DATAP0: U4.L1(CSI_DATAP0_DVP_D1) U7.E5(MDP0)
CSI_DATAP1: U4.M3(CSI_DATAP1_DVP_D3) U7.F3(MDP1)
DDR_VREF: C244.2 R346.1 R347.2 U4.E5(DDR_VREF)
DOVDD1V8: C11.1 C12.1 C34.1 C43.1 C44.1 C63.1 C88.1 C140.1 C143.1 C187.1 C248.1 C250.1 C255.1 FB7.1 L3.2 R8.2 R30.1 R32.1 R33.1 R34.1 R35.1 R343.1 TP2.1 U4.B8(DDRPLL_VCCA) U4.D3(PLL_AVDD) U4.K2(VDDIO18_2) U4.K3(CSI_VCCA18) U4.L17(VDDIO_RTC) U4.N11(VDDIO18_1) U4.N16(SADC_VREFP) U4.N17(SADC_AVDD) U4.T3(USB_AVD18) U7.D4(DOVDD_1) U7.E2(DOVDD_2)
EFUSE_AVDD: R14.1 U4.D4(EFUSE_AVDD)
EN_DLDO: R50.1 R51.1 U4.U15(EN_DLDO)
EXCLKI: C21.2 R17.2 U4.C1(EXCLK_XIN) Y1.1
EXCLKO: C25.2 R17.1 U4.D2(EXCLK_XOUT) Y1.3
FACTORY_RESET: C72.1 D1.2(CATHODE) R53.2 SW2.2 U4.C12(DMIC_DAT1_UART4_RXD_PB30)
G: J8.8 R56.1
HPOUTL: C27.2 U4.T1(HPOUTL)
IRCUTN: R29.1 U4.E17(MSC1_D1_PB18) U9.5(BIN)
IRCUTP: R28.1 U4.E16(MSC1_D0_PB17) U9.8(AIN)
IRLED_EN: R55.1 TP19.1 U4.C8(SMB1_SCK_PC20)
LDR1: C73.1 J8.6 R58.2 TP20.1 U4.P15(SADC_VIN0)
LED_G: R56.2 TP21.1 U4.C6(SMB2_SCK_PC09)
LED_R: R54.1 U4.C5(I2S_DAC_MCLK_PC11)
LINK/ACT: J3.11 R99.1 TP5.1
M0: R42.1 U4.A3(SSI_SLV_CE0_I2S_DAC_LRCK_PC16) U12.19(1B)
M1: R43.1 U4.B3(SSI_SLV_DT_I2S_SDTO_PC17) U12.20(2B)
M2: R44.2 U4.B4(SSI_SLV_CLK_I2S_DAC_BCLK_PC15) U12.1(3B)
M3: R45.2 U4.B5(SSI_SLV_DR_I2S_SDTI_PC18) U12.2(4B)
M4: R46.2 U4.A5(I2S_ADC_MCLK_PC12) U12.3(5B)
M5: R47.2 U4.B6(SMB2_SDA_PC08) U12.4(6B)
M6: R48.2 U4.B7(I2S_ADC_BCLK_PC13) U12.5(7B)
M7: R49.2 U4.A7(SMB1_SDA_PC19) U12.6(8B)
MCLK: R57.2 U4.E1(SA1_DVP_MCLK_PA15)
MICBIAS: C68.1 C69.1 R20.2 U4.P3(MICBIAS)
MICNL: C22.1 C71.2 J1.1 R15.1 R18.1
MICPL: C22.2 C70.2 J1.2 R18.2 R19.2
MINNL: C71.1 U4.P2(MICNL)
MINPL: C70.1 U4.N3(MICPL)
MSC0_CLK_PB04: D3.1(ANODE) J32.5(CLK) R207.1 TP48.1
MSC0_CMD_PB05: D4.1(ANODE) J32.3(CMD) R210.2 TP44.1 U4.G17(MSC0_CMD_PB05)
MSC0_D0_PB00: D5.1(ANODE) J32.7(DAT0) R209.2 TP43.1 U4.H16(MSC0_D0_PB00)
MSC0_D1_PB01: D6.1(ANODE) J32.8(DAT1) R211.2 TP45.1 U4.J15(MSC0_D1_PB01)
MSC0_D2_PB02: D7.1(ANODE) J32.1(DAT2) R212.2 TP46.1 U4.G15(MSC0_D2_PB02)
MSC0_D3_PB03: D8.1(ANODE) J32.2(DAT3) R213.2 TP47.1 U4.G16(MSC0_D3_PB03)
MVDD: C39.1 R27.2 U7.B5(MVDD)
PHY_AVDDL_REG: C74.1 C76.1 U4.R16(AVDDL_REG)
PHY_LED0: R99.2 U4.R13(LED0)
PHY_LED1: R100.2 U4.R15(LED1)
PHY_RST: C176.1 R52.1 U4.A11(DMIC_CLK_SMB2_SCK_PB28) U4.T13(PHY_RST)
POR_CTRL: R343.2 U4.K16(POR_CTL)
PWDN_PA19: R33.2 U4.E2(WAIT_PA19) U7.A4(PWDNB)
RD_N: J3.5 U4.U17(RD_N)
RD_P: J3.6 U4.T17(RD_P)
RX_DV: R313.1 U4.P14(RX_DV)
RXD3: R314.1 R315.1 U4.R14(RXD3)
RZQ: R75.1 U4.D9(RZQ)
SD0_CD_N: C150.2 D9.1(ANODE) J32.9(CD) Q1.1(GATE) R214.2 U4.C10(SMB1_SCK_UART3_RXD_PB26)
SENSOR_MCLK: R57.1 U7.C2(MCLK)
SENSOR_RESET: C35.2 R34.2 U4.E3(SA2_PA18) U7.C4(RESETB)
SFC_CS_N: R12.1 U4.T4(SFC0_CE_PA28) U13.1(C\S\)
SFC_SCLK: U4.R6(SFC0_CLK_PA27) U13.6(SCLK)
SFC_SIO0: U4.U5(SFC0_DT_IO0_PA23) U13.5(SI/SIO0)
SFC_SIO1: U4.R5(SFC0_DR_IO1_PA24) U13.2(SO/SIO1)
SFC_SIO2: U4.T5(SFC0_WP_IO2_PA26) U13.3(W\P\/SIO2)
SFC_SIO3: U4.T6(SFC0_HOLD_IO3_PA25) U13.7(H\O\L\D\/SIO3)
SID: R35.2 R36.2 U7.A5(SID)
SMB0_SCK: R30.2 U4.J4(SD7_SMB0_SCK_PA13) U7.A3(SCL)
SMB0_SDA: R32.2 U4.J1(SD6_SMB0_SDA_PA12) U7.B3(SDA)
SOC_0V8: C2.1 C4.1 C6.2 C48.1 C61.1 C86.1 C90.2 C203.1 C206.1 C212.1 C213.1 C214.1 C215.1 C216.1 C217.1 C218.1 L1.2 R5.2 TP25.1 U4.H5(VDD1) U4.H6(VDD2) U4.H7(VDD3) U4.H8(VDD4) U4.H9(VDD5) U4.H10(VDD6) U4.H11(VDD7) U4.H12(VDD8) U4.H13(VDD9) U4.J5(VDD10) U4.J13(VDD11) U4.K5(VDD12) U4.K13(VDD13) U4.L5(VDD14) U4.L15(VDD_RTC) U4.M5(VDD15) U4.M6(VDD16) U4.N2(CSI_VCCA08) U4.N6(VDD17) U4.N7(VDD18) U4.N8(VDD19) U4.N9(VDD20) U4.N10(VDD21) U4.R4(USB_AVD08)
SOC_3V3: C5.1 C7.1 C17.2 C49.1 C65.1 C75.1 C91.2 C96.1 C144.1 C148.1 C149.1 C150.1 C189.1 L2.2 Q1.2(SOURCE) Q2.2(SOURCE) R3.2 R12.2 R16.2 R23.2 R38.1 R40.1 R51.2 R52.2 R53.1 R59.2 R60.2 R68.1 R69.2 R214.1 R313.2 R314.2 TP1.1 U4.C4(VDDIO2) U4.J14(VDDIO1_2) U4.P9(VDDIO1_1) U4.R3(USB_AVD33) U10.1(VIN) U11.1(VIN) U13.8(VCC)
SOC_DDR: C15.1 C16.1 C231.1 C232.1 C233.1 C234.1 C238.1 C239.1 C240.1 C241.1 L4.2 R11.2 R346.2 TP3.1 U4.E6(VDDMEM1) U4.E7(VDDMEM2) U4.E8(VDDMEM3) U4.E9(VDDMEM4) U4.E10(VDDMEM5) U4.E11(VDDMEM6) U4.E12(VDDMEM7) U4.F5(DDRVDD1) U4.F6(DDRVDD2) U4.F7(DDRVDD3) U4.F8(DDRVDD4) U4.F9(DDRVDD5) U4.F10(DDRVDD6) U4.F11(DDRVDD7) U4.F12(DDRVDD8)
SPEAK_EN_PB31: R22.1 U4.B10(GPIO_PB31)
SPEED: J3.12 R100.1 TP6.1
TD_N: J3.8 U4.U16(TD_N)
TD_P: J3.9 U4.T16(TD_P)
UART1_RXD: J3.13 U4.F16(UART1_RXD_PB24)
UART1_TXD: J3.14 U4.F15(UART1_TXD_PB23)
USB_DM: U4.U1(USB0PN) U14.3(D-)
USB_DP: U4.T2(USB0PP) U14.2(D+)
VCM: C66.1 C67.1 U4.R2(VCM)
VOTP: TP24.1 U7.E7(VOTP)
WIFI_3V3: C84.1 C89.1 Q2.3(DRAIN) R68.2 U14.4(3V3)
WIFI_PWR_EN: R70.1 U4.C11(SMB1_SDA_UART3_TXD_PB25)
ZQ: R345.1 U4.F13(DDR_ZQ)
N16068033: J4.2 U9.4(AOUT)
N16068049: J4.1 U9.2(BOUT)
N16494121: C83.1 C97.2 U14.5(ANT1)
N16494125: C83.2 J9.3 L5.1
N16658117: C91.1 Q2.1(GATE) Q3.3(COLLECTOR) R69.1
N16658257: Q3.1(BASE) R70.2 R71.2
N16680846: C38.1 R38.2 U10.3(EN)
N16681558: C50.1 R40.2 U11.3(EN)
N16842331: J8.3 R54.2 TP18.1
N17912916: C5.2 R3.1 R4.2 U1.5(FB)
N17912932: L2.1 U1.3(LX)
N17913000: C3.1 R1.2 U1.1(EN)
N17913512: C10.1 R2.2 U2.1(EN)
N17913867: C14.1 R7.2 U3.1(EN)
N17913916: L3.1 U3.3(LX)
N17913918: C11.2 R8.1 R9.2 U3.5(FB)
N17914253: C20.1 R10.2 U5.1(EN)
N17914314: C15.2 R11.1 R13.2 U5.5(FB)
N17914320: L4.1 U5.3(LX)
N17923584: C23.1 C24.1 R19.1 R20.1
N17923959: R21.1 R22.2 U6.1(/SD)
N17923983: J2.2 U6.5(VO+)
N17923995: J2.1 U6.8(VO-)
N17924016: R26.1 U6.4(-IN)
N17924026: C27.1 R26.2
N17924036: C26.1 R24.2
N17924072: R24.1 U6.3(+IN)
N17926744: C32.2 U7.D7(TXLOW)
N17926746: C33.2 U7.F7(VREF)
N17992613: C6.1 R5.1 R6.1 U2.5(FB)
N17994204: L1.1 U2.3(LX)
N18040120: R312.1 U4.T15(RBIAS)
N18040755: R207.2 U4.H15(MSC0_CLK_PB04)
N18061971: C52.1 U10.4(BP/FB)
N18083960: R16.1 U4.T10(GMAC_MDIO_SMB2_SCK_PB11)
N18093878: R23.1 U4.R10(GMAC_MDCK_SMB2_SDA_PB10)
N179301303: J8.4 R55.2

Pads without a net: J8 5; M* 1; M*#2 1; M*#3 1; NOREF#2 1; NOREF#5 1; NOREF#8 1; NOREF#9 1; NOREF#16 1; U4 A1 A2 A13 A15 A16 A17 B1 B2 B11 B12 B13 B14 B15 B16 B17 C2 C3 C7 C13 C14 C15 C16 C17 D14 D15 D16 E15 F2 F3 G1 G2 G3 H2 H3 J2 J3 J16 J17 K15 L13 L16 M15 M16 N15 P16 R7 R8 R9 R11 R12 R17 T7 T8 T9 T11 T12 U2 U3 U7 U9 U11 U13; U6 2; U7 A2 A6 B2 B6 C5 C6 C7 D1 D3 D5 E1 F1 F2; U9 6; U11 4; U12 7 18

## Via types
v1: diameter 0.406, hole 0.203, TOP to BOTTOM, 641 vias

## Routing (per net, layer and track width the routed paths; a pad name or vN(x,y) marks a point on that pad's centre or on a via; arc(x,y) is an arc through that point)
AGND: length 20.7
  TOP w0.203: C52.2 23.69,64.52 19.63,64.52 R39.1
  TOP w0.254: C41.2 v1(28.24,74.77) 27.88,74.77 C42.2 27.58,74.47 U7.B1 ; v1(21.23,74.47) U7.B7
  TOP w0.305: v1(21.23,74.47) 20.24,74.47 C40.2 19.44,75.27 C32.1 C33.1
  L3_GND w0.406: v1(21.23,74.47) 22.12,74.47 22.39,74.73 23.77,74.73 24.99,73.51 26.99,73.51 v1(28.24,74.77)
AVDD2V8: length 14.1
  TOP w0.254: v1(20.83,73.82) U7.A7 ; C41.1 28.77,73.62 v1(28.25,73.62) C42.1 27.54,73.82 U7.A1
  TOP w0.305: v1(20.83,73.82) 20.07,73.82 C40.1 R37.2
  L3_GND w0.406: v1(28.25,73.62) 27.85,73.62 27.21,72.98 24.77,72.98 24.21,73.54 21.98,73.54 21.7,73.82 v1(20.83,73.82)
DVDD1V2OUT: length 3
  BOTTOM w0.254: U4.T14 29.54,88.7 28.69,88.7 C175.1 C79.1
DVDD1V3: length 26.8
  TOP w0.254: U7.D6 v1(22.33,75.43) ; C45.1 v1(27.22,75.12) U7.C1
  TOP w0.305: U11.5 27.07,65.96 26.81,66.22 C47.1 25.78,68.89 26.34,69.45 v1(30.33,69.45)
  L3_GND w0.406: v1(22.33,75.43) 26.1,75.43 26.41,75.12 v1(27.22,75.12)
  BOTTOM w0.254: C46.1 22.03,75.43 v1(22.33,75.43) 22.65,75.43 R27.1
  BOTTOM w0.406: v1(30.33,69.45) 31.37,70.49 31.37,72.8 30,74.17 27.63,74.17 27.22,74.58 v1(27.22,75.12)
GND: length 62.1
  TOP w0.102: 22.34,77.07 U7.F6 ; U7.F6 22.39,76.78 ; U7.F6 22.67,77.39 ; U7.F6 22.39,77.35 ; 22.67,76.09 U7.E6 ; U7.E6 22.39,76.13 ; U7.E6 22.39,76.7 ; U7.E6 22.34,76.42 ; U7.D2 25.92,75.77 ; U7.D2 25.59,75.44 ; U7.D2 25.31,75.48 ; U7.D2 25.87,76.05 ; 24.58,75.4 U7.C3 ; U7.C3 24.58,74.83 ; U7.C3 25.14,74.83 ; U7.C3 25.14,75.4
  TOP w0.254: D2.2 v1(17.18,93.15)
  BOTTOM w0.102: 35.27,87.93 v1(35.27,87.93)
  BOTTOM w0.152: U4.K7 v1(33.32,84.68) ; U4.G13 35.27,87.93 ; U4.L11 v1(32.67,87.28) ; v1(32.66,88.58) U4.M13 v1(32.02,88.58) ; U4.L7 v1(32.67,84.03) ; U4.G9 v1(35.27,85.98) ; U4.K6 v1(33.32,84.03) U4.L6 ; U4.G5 v1(35.27,83.38) U4.G6 ; U4.J9 33.97,85.33 U4.J8 ; U4.N12 v1(31.37,87.93) ; U4.L12 v1(32.67,87.93) ; U4.K10 v1(33.32,86.63) 33.32,86.63 U4.K11 ; U4.P4 31.11,82.47 31.11,83.12 v1(31.37,83.38) ; U4.L10 v1(32.67,86.63) ; U4.L8 v1(32.67,85.33) ; U4.M12 v1(32.02,87.93) ; U4.G12 v1(35.27,87.93) ; U4.K8 v1(33.32,85.33) ; U4.G7 v1(35.27,84.68) ; U4.G11 v1(35.27,87.28)
  BOTTOM w0.203: U4.J6 U4.J7 33.97,84.68 ; U4.J11 U4.K11 ; U4.J12 U4.K12 ; U4.J10 U4.K10
  BOTTOM w0.254: Y1.4 39.53,77.64 ; Y1.4 38.85,77.66 ; Y1.4 38.85,76.4 ; Y1.4 39.53,77.03 ; Y1.2 37.68,75.48 ; Y1.2 37,74.85 ; Y1.2 36.32,75.48 ; Y1.2 37,76.11 ; J32.11 12.68,100.79 ; J32.6 v1(17.18,93.15) ; U4.C9 v1(37.87,85.33) ; U4.N5 v1(31.37,83.38)
  BOTTOM w0.508: HOLE2.1 42.57,94.15 v1(42.57,90.53) v1(42.57,87.36) v1(42.57,85.4) v1(42.57,84.56) v1(42.57,83.27) v1(42.57,80.14) v1(42.57,77.88) v1(42.57,75.42) v1(42.57,74.35) v1(42.57,67.77) C51.2
  vias: v1(5.74,89.44) v1(5.74,88.66) v1(5.74,86.45) v1(5.74,85.67) v1(5.71,80.88) v1(5.74,80.22) v1(5.77,71.67) v1(5.77,70.66) v1(5.77,69.64) v1(5.74,58.53) v1(5.71,57.72) v1(5.82,97.64) v1(5.84,96.02) v1(5.84,92.11) v1(5.79,78.25) v1(5.79,77.24) v1(5.79,76.22) v1(5.79,75.2) v1(5.98,55.94) v1(5.99,93.53) v1(6.12,65.26) v1(6.12,64.24) v1(6.1,63.43) v1(6.12,62.46) v1(6.1,61.65) v1(6.12,60.81) v1(6.1,60) v1(6.45,94.51) v1(6.57,56.5) v1(6.86,63.05) v1(6.86,62.16) v1(6.86,60.51) v1(6.86,59.75) v1(6.88,64.88) v1(6.88,63.86) v1(6.88,61.32) v1(7.16,87.53) v1(7.32,98.74) v1(7.49,65.34) v1(7.67,94.29) v1(8.1,65.51) v1(8.48,99.59) v1(8.53,65.08) v1(8.76,94.09) v1(9.04,62.34) v1(9.02,61.53) v1(9.09,59.9) v1(9.5,99.59) v1(9.5,98.57) v1(9.5,77.24) v1(9.65,63.3) v1(9.65,56.57) v1(9.78,61.27) v1(9.78,59.62) v1(9.8,87.53) v1(9.8,62.08) v1(9.8,60.43) v1(9.98,73.49) v1(9.98,72.52) v1(10.13,95.79) v1(10.11,62.64) v1(10.36,89.26) v1(10.46,56.55) v1(10.52,100.6) v1(10.52,99.59) v1(10.52,98.57) v1(10.57,84.36) v1(10.57,58.53) v1(10.54,57.72) v1(10.52,55.9) v1(10.52,54.88) v1(10.52,53.87) v1(10.64,85.93) v1(10.67,79.2) v1(10.67,61.27) v1(10.72,74.89) v1(10.72,60.41) v1(10.72,59.39) v1(11.13,66.91) v1(11.35,84.31) v1(11.53,100.6) v1(11.53,99.59) v1(11.53,98.57) v1(11.53,89.43) v1(11.53,78.25) v1(11.53,77.24) v1(11.53,73.17) v1(11.56,72.24) v1(11.53,61.07) v1(11.53,59.96) v1(11.53,58.95) v1(11.53,57.93) v1(11.53,56.92) v1(11.53,55.9) v1(11.53,54.88) v1(11.53,53.87) v1(11.71,87.53) v1(11.84,67.27) v1(11.91,69.63) v1(12.32,90.84) v1(12.47,85.63) v1(12.55,101.62) v1(12.55,100.6) v1(12.55,99.59) v1(12.55,98.57) v1(12.55,80.28) v1(12.55,73.17) v1(12.55,59.96) v1(12.55,58.95) v1(12.55,57.93) v1(12.55,56.92) v1(12.55,55.9) v1(12.55,54.88) v1(12.55,53.87) v1(12.83,89.41) v1(12.83,67.29) v1(13,91.73) v1(13.23,84.64) v1(13.56,101.62) v1(13.56,100.6) v1(13.56,99.59) v1(13.56,98.57) v1(13.56,73.17) v1(13.51,66.33) v1(13.56,58.95) v1(13.56,57.93) v1(13.56,56.92) v1(13.56,55.9) v1(13.74,87.46) v1(13.74,84.16) v1(14.02,63.61) v1(14.12,88.98) v1(14.3,90.63) v1(14.48,67.47) v1(14.58,101.62) v1(14.58,100.6) v1(14.58,99.59) v1(14.58,73.17) v1(14.5,69.83) v1(14.58,57.93) v1(14.58,56.92) v1(14.58,55.9) v1(14.6,93.3) v1(14.63,86.59) v1(14.99,64.17) v1(15.01,63.15) v1(15.24,67.47) v1(15.32,70.01) v1(15.29,62.03) v1(15.6,101.62) v1(15.6,100.6) v1(15.6,88.41) v1(15.6,85.36) v1(15.6,84.35) v1(15.6,83.33) v1(15.6,82.32) v1(15.6,73.17) v1(15.6,56.92) v1(15.6,55.9) v1(15.6,54.88) v1(15.6,53.87) v1(15.7,77.43) v1(15.93,87.74) v1(16.03,81.05) v1(16.61,102.64) v1(16.61,101.62) v1(16.61,93.49) v1(16.61,86.51) v1(16.61,85.36) v1(16.61,84.35) v1(16.61,83.33) v1(17.04,81.05) v1(17.25,96.04) v1(17.37,90.71) v1(17.37,88.83) v1(17.63,103.65) v1(17.63,102.64) v1(17.63,86.51) v1(17.63,85.36) v1(17.63,84.35) v1(17.73,87.59) v1(17.86,95.82) v1(17.78,71.67) v1(17.78,70.66) v1(17.78,67.86) v1(17.78,66.85) v1(17.88,78.01) v1(17.93,62.16) v1(18.06,64.93) v1(18.14,82.07) v1(18.29,63.1) v1(18.44,78.57) v1(18.52,97.19) v1(18.64,103.65) v1(18.64,102.64) v1(18.64,89.43) v1(18.64,86.51) v1(18.64,85.36) v1(18.69,82.66) v1(18.75,60.94) v1(18.82,90.58) v1(18.9,87.59) v1(18.94,62.62) v1(19.05,96.6) v1(19.13,97.87) v1(19.46,79.56) v1(19.66,103.65) v1(19.66,102.64) v1(19.63,93.76) v1(19.66,86.51) v1(19.66,78.25) v1(20.02,62.8) v1(20.12,93.25) v1(20.17,87.59) v1(20.19,98.33) v1(20.24,56.78) v1(20.37,63.71) v1(20.45,96.25) v1(20.47,55.28) v1(20.68,103.65) v1(20.68,102.64) v1(20.68,78.25) v1(20.68,73.17) v1(20.83,79.58) v1(21.03,95.82) v1(21.06,70.57) v1(21.06,69.42) v1(21.08,98.3) v1(21.34,94.49) v1(21.39,75.04) v1(21.54,87.59) v1(21.69,103.65) v1(21.69,102.64) v1(21.69,85.36) v1(21.69,70.12) v1(21.69,63.76) v1(21.74,53.09) v1(21.79,83.83) v1(21.97,90.63) v1(21.93,69.02) v1(21.93,68) v1(22.07,94.49) v1(22.02,79.36) v1(22,66.3) v1(22.15,65.28) v1(22.25,99.04) v1(22.22,96.2) v1(22.35,76.74) v1(22.5,77.58) v1(22.5,63.76) v1(22.61,86.52) v1(22.63,78.24) v1(22.71,103.65) v1(22.71,70.12) v1(23.06,67.8) v1(23.04,66.87) v1(23.11,96.07) v1(23.09,80.42) v1(23.27,78.11) v1(23.47,98.46) v1(23.47,72.96) v1(23.57,53.14) v1(23.6,85.27) v1(23.72,103.65) v1(23.72,79.27) v1(23.72,57.93) v1(23.88,96.2) v1(24.05,66.87) v1(24.13,67.74) v1(24.28,98.46) v1(24.33,81.18) v1(24.51,85.68) v1(24.54,74.79) v1(24.49,55.68) v1(24.59,79.15) v1(24.74,103.65) v1(24.74,102.64) v1(24.74,79.94) v1(24.74,64.03) v1(24.84,64.07) v1(25.04,98.51) v1(25.15,67.74) v1(25.1,66.86) v1(25.3,58.73) v1(25.4,90.79) v1(25.4,90) v1(25.4,81.18) v1(25.5,55.68) v1(25.65,99.12) v1(25.65,69.65) v1(25.65,53.14) v1(25.76,103.65) v1(25.76,102.64) v1(25.81,79.76) v1(25.81,64.57) v1(25.81,63.56) v1(25.93,78.62) v1(25.91,76.09) v1(25.96,74.73) v1(26.01,54.41) v1(26.26,58.73) v1(26.26,53.14) v1(26.37,98.23) v1(26.61,87.08) v1(26.77,103.65) v1(26.77,102.64) v1(26.77,67.08) v1(26.77,64.03) v1(26.92,84.66) v1(27.03,83.85) v1(27.08,79.76) v1(27,78.59) v1(27.08,58.73) v1(27.15,98.63) v1(27.41,84.66) v1(27.66,98.08) v1(27.84,91.65) v1(27.79,66.06) v1(27.79,65.04) v1(27.79,57.93) v1(28.04,89.44) v1(28.02,88.83) v1(27.99,76.51) v1(28.4,81.82) v1(28.4,54.46) v1(28.55,77.6) v1(28.57,71.94) v1(28.57,53.17) v1(28.63,85.23) v1(28.7,91.65) v1(28.8,97.64) v1(29.29,76.51) v1(29.31,71.94) v1(29.39,53.17) v1(29.64,97.62) v1(29.62,91.55) v1(29.82,103.65) v1(29.82,102.64) v1(29.82,75.2) v1(29.82,73.46) v1(29.82,65.04) v1(30.02,77.6) v1(30.18,57.97) v1(30.18,57.16) v1(30.18,56.19) v1(30.33,66.33) v1(30.35,65.54) v1(30.72,85.98) v1(30.68,72.73) v1(30.84,102.64) v1(30.84,75.2) v1(30.84,74.19) v1(30.89,76.51) v1(31.09,78.19) v1(31.24,101.86) v1(31.24,101.1) v1(31.24,90.68) v1(31.22,78.95) v1(31.67,68.94) v1(31.7,59.04) v1(31.85,102.64) v1(31.85,101.62) v1(31.85,75.2) v1(31.85,74.19) v1(31.85,73.17) v1(31.98,77.4) v1(32,89.11) v1(32.16,75.93) v1(32.38,77.81) v1(32.44,67.95) v1(32.61,82.25) v1(32.87,102.64) v1(32.87,101.62) v1(32.87,73.17) v1(33.02,99.63) v1(33.17,71.48) v1(33.17,58.73) v1(33.17,58.12) v1(33.38,93.38) v1(33.43,100.34) v1(33.62,78.22) v1(33.83,98.15) v1(33.83,97.64) v1(33.88,102.64) v1(33.88,101.62) v1(33.88,99.63) v1(33.88,73.17) v1(33.88,67.08) v1(33.88,66.06) v1(34.01,78.7) v1(34.19,92.87) v1(34.62,81.43) v1(34.65,58.81) v1(34.65,56.45) v1(34.9,101.62) v1(34.9,70.52) v1(35.86,88.63) v1(35.79,77.25) v1(35.81,70.52) v1(36.42,99.88) v1(36.4,66.43) v1(36.4,65.67) v1(36.4,64.7) v1(36.55,53.17) v1(36.78,70.52) v1(37.16,66.43) v1(37.16,65.67) v1(37.16,64.7) v1(37.29,99.88) v1(37.37,55.8) v1(37.69,70.52) v1(37.95,100.6) v1(37.95,99.59) v1(37.95,96.54) v1(37.92,66.43) v1(37.92,65.67) v1(37.92,64.7) v1(37.95,56.32) v1(38.1,98.71) v1(38.1,97.85) v1(38.25,59.54) v1(38.38,92.67) v1(38.51,91.34) v1(38.52,89.88) v1(38.51,71.79) v1(38.58,74) v1(38.58,53.19) v1(38.76,92.01) v1(38.71,70.82) v1(38.96,99.59) v1(38.96,98.57) v1(38.94,77.91) v1(38.96,74.48) v1(39.17,91.34) v1(39.17,89.88) v1(39.17,87.93) v1(39.24,79.05) v1(39.24,60.2) v1(39.42,88.91) v1(39.5,79.69) v1(39.52,70.8) v1(39.98,99.59) v1(40.23,82.3) v1(40.56,71.74) v1(40.67,92.36) v1(40.64,88.45) v1(40.67,87.51) v1(40.89,66.99) v1(41,98.57) v1(41,94.51) v1(41.07,83.19) v1(41,56.92) v1(41.1,91.83) v1(41.48,70.62) v1(41.48,69.45) v1(41.4,67.49) v1(42.01,94.51) v1(42.01,93.49) v1(42.01,57.93) v1(42.01,56.92) v1(42.04,55.78) v1(42.01,53.14) v1(42.47,97.59) v1(42.47,54.29) v1(42.52,95.38) v1(42.57,67.01) v1(42.52,64.22) v1(42.52,63.48) v1(42.49,61.93)
VCC_5V: length 26
  TOP w0.203: U5.4 30.29,98.8 31.19,97.9 31.19,96.53 32.15,95.57 R10.1 ; U1.4 12.26,66.76 13.11,66.76 14.07,67.72 R1.1 ; U2.4 24.85,99.84 23.98,98.96 22.82,98.96 R2.1 21.6,97.74 C9.1
  TOP w0.254: U3.4 33.42,57.25 34.39,58.22 35.69,58.22 36.65,59.19 R7.1
  TOP w0.406: C31.1 v1(9.91,82.47) 10.72,82.47 10.92,82.68 U9.1
  BOTTOM w0.406: C28.1 v1(8.64,77.78) 10.41,77.78 10.99,77.2 U6.6
  vias: v1(6.45,68.84) v1(6.86,67.88) v1(6.98,90.74) v1(7.24,68.84) v1(7.72,67.88) v1(7.87,90.74) v1(8.03,68.84) v1(8.25,91.24) v1(9.14,91.5) v1(9.52,92.04) v1(17.02,54.46) v1(17.02,53.6) v1(17.88,54.46) v1(17.88,53.6) v1(18.54,54.46) v1(26.92,100.77) v1(27.3,100.01) v1(27.81,100.77) v1(28.19,100.01) v1(28.7,100.77) v1(32,55.18) v1(32.77,55.18) v1(33.53,55.18)
VDDMSC0: length 15.5
  TOP w0.254: R210.1 R213.1 R212.1 ; R210.1 19.56,92.97 v1(19.38,93.15) ; R210.1 R209.1 R211.1
  TOP w0.508: Q1.3 16.27,94.13 C146.1 18.75,94.13 C147.1 18.8,93.18 D2.1 v1(19.38,93.15)
  BOTTOM w0.508: J32.4 v1(19.38,93.15)
A0+: length 19.1
  BOTTOM w0.305: U12.14 36.71,63.18 36.32,62.8
  BOTTOM w0.508: 36.32,62.8 35.92,62.39 30.33,62.39 TP12.1 27.3,59.37 21.72,59.37 20.98,58.63 J6.2
A0-: length 21.1
  BOTTOM w0.254: U12.16 35.07,64.4
  BOTTOM w0.508: J6.4 17.98,59.19 19.68,60.89 26.04,60.89 TP10.1 28.8,63.66 34.33,63.66 35.07,64.4
A1+: length 11
  BOTTOM w0.254: 39.16,64.44 U12.10
  BOTTOM w0.508: 39.16,64.44 39.16,61.57 37.39,59.8 34.22,59.8 TP17.1 J7.2
A1-: length 11.4
  BOTTOM w0.254: 37.8,62.96 37.71,63.06 U12.12
  BOTTOM w0.508: 37.8,62.96 37.8,62.25 36.67,61.11 32.54,61.11 TP15.1 J7.4
B0+: length 20.2
  BOTTOM w0.254: 36.01,63.43 U12.15
  BOTTOM w0.508: J6.3 19.48,59.16 20.45,60.13 26.67,60.13 TP11.1 29.57,63.02 35.6,63.02 36.01,63.43
B0-: length 23.1
  BOTTOM w0.305: 34.49,64.85 34.73,65.09 U12.17
  BOTTOM w0.508: 34.49,64.85 33.93,64.29 28.04,64.29 TP9.1 25.4,61.65 18.41,61.65 16.48,59.72 J6.5
B1+: length 10.8
  BOTTOM w0.254: 38.48,63.37 U12.11
  BOTTOM w0.508: 38.48,63.37 38.48,61.91 37.03,60.46 33.38,60.46 TP16.1 J7.3
B1-: length 12.2
  BOTTOM w0.305: 37.08,62.54 37.21,62.67 U12.13
  BOTTOM w0.508: J7.5 TP14.1 29.44,59.8 31.39,61.75 36.29,61.75 37.08,62.54
BOOTSEL0: length 2.8
  BOTTOM w0.102: R59.1 41.66,86.65 40.72,85.71 39.54,85.71 U4.A9
BOOTSEL1: length 6.6
  BOTTOM w0.102: R61.2 40.65,90.1 R60.1 41.2,88.62 41.2,86.59 40.56,85.96 39.33,85.96 39.03,85.66 U4.B9
CODEC_AVDD: length 4.5
  TOP w0.305: FB7.2 29.84,80.32 v1(29.46,79.94) 28.9,79.94 C53.1 28.01,80.83 C54.1
  BOTTOM w0.254: v1(29.46,79.94) 29.87,79.94 U4.R1
CSI_CLKN: length 15.2
  TOP w0.104: v1(24.13,78.82) 24.12,78.82 23.72,78.42 23.72,77.04 24.13,76.64 U7.E4
  BOTTOM w0.104: v1(24.13,78.82) 24.26,78.7 25.2,78.7 25.7,78.19 26.49,78.19 27.48,77.2 30.77,77.2 32.05,78.48 32.05,78.77 31.94,78.89 31.73,78.89 31.62,78.99 31.62,79.22 31.73,79.33 31.94,79.33 32.05,79.44 32.05,80.72 32.34,81 U4.M2
CSI_CLKP: length 15.2
  TOP w0.104: v1(24.13,78.29) 24,78.16 24,77.94 24.11,77.84 24.39,77.84 24.49,77.75 24.49,77.57 24.39,77.48 24.07,77.48 24,77.41 24,77.19 U7.F4
  BOTTOM w0.104: U4.L3 32.64,81.41 32.64,80.91 32.33,80.6 32.33,78.37 30.89,76.92 27.37,76.92 26.38,77.91 25.59,77.91 25.08,78.42 24.26,78.42 v1(24.13,78.29)
CSI_DATAN0: length 15.1
  TOP w0.104: U7.F5 v1(23.08,77.39)
  BOTTOM w0.104: U4.L2 32.99,80.93 32.64,80.58 32.64,79.91 32.92,79.64 32.92,77.74 31.28,76.1 27.2,76.1 26.1,77.21 23.26,77.21 v1(23.08,77.39)
CSI_DATAN1: length 15.2
  TOP w0.104: v1(26.51,78.95) 26.38,79.07 25.69,79.07 25.17,78.55 25.17,76.95 24.86,76.64 U7.E3
  BOTTOM w0.104: v1(26.51,78.95) 26.63,79.07 27.32,79.07 27.42,78.97 27.42,78.18 27.69,77.91 28.13,77.91 28.4,78.18 28.4,79.22 28.5,79.33 28.71,79.33 28.81,79.22 28.81,78.05 29.08,77.78 29.52,77.78 29.79,78.05 29.79,78.97 29.89,79.07 30.26,79.07 30.46,79.27 30.59,79.27 30.71,79.16 30.84,79.16 30.93,79.25 30.93,79.38 30.81,79.5 30.81,79.62 30.91,79.72 31.03,79.72 31.15,79.6 31.28,79.6 31.37,79.69 31.37,79.82 31.26,79.94 31.26,80.07 31.64,80.46 U4.N1
CSI_DATAP0: length 15.2
  TOP w0.104: U7.E5 v1(23.08,76.74)
  BOTTOM w0.104: v1(23.08,76.74) 23.26,76.93 25.99,76.93 27.09,75.83 31.39,75.83 33.2,77.63 33.2,78.49 33.3,78.59 33.4,78.59 33.5,78.7 33.5,78.91 33.4,79.01 33.3,79.01 33.2,79.11 33.2,79.75 32.92,80.03 32.92,80.38 U4.L1
CSI_DATAP1: length 15.3
  TOP w0.104: U7.F3 24.89,77.1 24.89,78.67 25.58,79.35 26.37,79.35 26.5,79.48 v1(26.51,79.48)
  BOTTOM w0.104: U4.M3 31.99,81.41 31.99,80.98 31.77,80.76 31.55,80.76 30.15,79.35 29.78,79.35 29.51,79.09 29.51,78.16 29.4,78.06 29.2,78.06 29.09,78.16 29.09,79.34 28.82,79.61 28.38,79.61 28.12,79.34 28.12,78.29 28.01,78.19 27.8,78.19 27.7,78.29 27.7,79.09 27.43,79.35 26.63,79.35 v1(26.51,79.48)
DDR_VREF: length 5.7
  TOP w0.203: v1(37.49,84.54) 38.5,84.54 C244.2 39.24,85.27 39.61,85.27 R347.2 40,85.67 R346.1
  BOTTOM w0.203: v1(37.49,84.54) 37.49,83.66 U4.E5
DOVDD1V8: length 103.9
  TOP w0.203: v1(32.51,69.27) 31.52,70.26 24.14,70.26 R34.1 23.09,71.29 R35.1 ; R8.2 36.67,58.27 C11.1 38.35,58.27 38.73,58.65 38.73,61.53 TP2.1
  TOP w0.254: R33.1 R30.1 R32.1 v1(30.48,71.29) ; v1(37.86,81.43) 37.86,80.84 C248.1 ; 30.27,86.59 C143.1 ; U7.D4 v1(24.45,76.09) ; U7.E2 v1(25.27,76.09)
  TOP w0.305: v1(33.99,79.3) 33.77,79.3 C187.1
  TOP w0.406: v1(30.06,82.08) 30.06,81.73 FB7.1 28.99,81.51 C63.1 ; v1(30.99,87.31) 30.27,86.59 ; C143.1 29.37,86.59 C140.1
  L2_PWR w0.152: 30.49,71.29 v1(30.48,71.29)
  L2_PWR w0.254: 35.43,69.02 36.8,67.65 40.79,67.65 41.94,68.79 41.94,72.02 41.58,72.37 41.58,84.33 40.91,85.01 v1(40.14,85.01)
  L2_PWR w0.305: v1(30.99,87.31) 30.86,87.43 30.86,88.73 31.85,89.72 31.85,91.34 v1(31.69,91.5)
  L2_PWR w0.508: v1(37.86,81.43) 37.86,79.71 36.96,78.8 35.05,78.8 34.54,79.31 33.99,79.31 ; v1(32.51,69.27) 30.49,71.29 ; v1(33.99,79.3) 32.98,79.3 32.66,79.61 30.71,79.61 30.35,79.25 28.68,79.25 27.81,80.12 27.81,83.06 ; v1(30.99,87.31) 30.06,86.38 v1(30.06,82.08)
  BOTTOM w0.254: U4.B8 v1(40.14,85.01) C250.1 ; R343.1 32.75,93.13 C255.1 ; R343.1 32.99,91.9 U4.L17 ; R343.1 32.75,92.14 C34.1 31.69,92.08 v1(31.69,91.5) U4.N17 U4.N16 ; 25.36,74.69 C43.1 ; U4.D3 v1(37.86,81.43) ; U4.N11 31.34,86.96 v1(30.99,87.31) ; U4.T3 v1(30.06,82.08) ; C88.1 v1(33.99,79.3) 33.99,79.78 33.64,80.13 U4.K2 U4.K3
  BOTTOM w0.406: 25.36,74.69 C44.1 25.36,76 v1(25.27,76.09) 25.26,76.09 v1(24.45,76.09) ; C43.1 25.34,74.1 26.75,72.7 29.67,72.7 30.48,71.89 v1(30.48,71.29)
  vias: v1(33.4,69.53)
EFUSE_AVDD: length 1.6
  TOP w0.254: v1(37.86,82.08) 38.6,81.35 R14.1
  BOTTOM w0.254: U4.D4 v1(37.86,82.08)
EN_DLDO: length 3.1
  TOP w0.102: R51.1 27.06,91.09 R50.1 28.77,89.39 v1(28.77,89.23)
  BOTTOM w0.102: U4.U15 v1(28.77,89.23)
EXCLKI: length 5.6
  BOTTOM w0.152: Y1.1 38.1,76.23 38.1,77.58 38.36,77.84 C21.2 38.57,78.49 R17.2 38.19,79.62 U4.C1
EXCLKO: length 4.3
  BOTTOM w0.152: Y1.3 37,77.83 C25.2 37.46,79.18 R17.1 37.54,79.26 U4.D2
FACTORY_RESET: length 25.2
  L2_PWR w0.102: v1(41.94,86.26) 41.22,86.26 40.54,86.95 39.49,86.95 v1(39.16,87.28)
  BOTTOM w0.102: v1(41.94,86.26) 41.99,86.26 42.14,86.42 42.14,92.41 41.08,93.47 39.31,93.47 35.63,97.14 34.86,97.14 R53.2 33.9,97.09 32.9,97.09 C72.1 D1.2 31.34,97.72 SW2.2 ; v1(39.16,87.28) 39.16,87.28 38.51,87.28 U4.C12
G: length 2.3
  TOP w0.102: J8.8 24.21,58.38 R56.1
HPOUTL: length 16.2
  BOTTOM w0.102: U4.T1 30.06,80.78 30.06,81.24 29.88,81.43 28.1,81.43
  BOTTOM w0.203: 28.1,81.43 27.91,81.62 23.65,81.62 21.08,79.05 C27.2
IRCUTN: length 41
  TOP w0.102: U9.5 14.73,89.35 R29.1 12.84,91.24 11.43,91.24 11.14,91.53 11.14,95.78 v1(11.3,95.94)
  BOTTOM w0.102: v1(11.3,95.94) 14.31,95.94 15.61,94.65 20.03,94.65 20.94,93.73 23.43,93.73 25.59,95.89 35.19,95.89 36.89,94.19 U4.E17
IRCUTP: length 40.9
  TOP w0.102: v1(11.3,96.7) 10.91,96.31 R28.1 10.91,88.82 U9.8
  BOTTOM w0.102: v1(11.3,96.7) 11.84,96.17 14.41,96.17 15.7,94.88 20.12,94.88 21.04,93.96 23.34,93.96 25.5,96.12 35.28,96.12 37.19,94.21 37.19,90.69 36.89,90.39 U4.E16
IRLED_EN: length 50.9
  TOP w0.102: R55.1 v1(26.01,55.05) TP19.1
  L2_PWR w0.102: v1(26.01,55.05) 30.07,55.05 31.01,54.11 36.63,54.11 42.11,59.59 42.11,68.21 42.47,68.57 42.47,72.4 42.19,72.68 42.19,85.55 42.01,85.73 v1(41.91,85.73)
  BOTTOM w0.102: U4.C8 38.51,85.33 39.81,85.33 39.95,85.48 40.94,85.48 41.2,85.73 v1(41.91,85.73)
